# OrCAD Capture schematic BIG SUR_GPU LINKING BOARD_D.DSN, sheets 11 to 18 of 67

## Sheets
11 P11  PLX Switch-1 Straping: size Custom
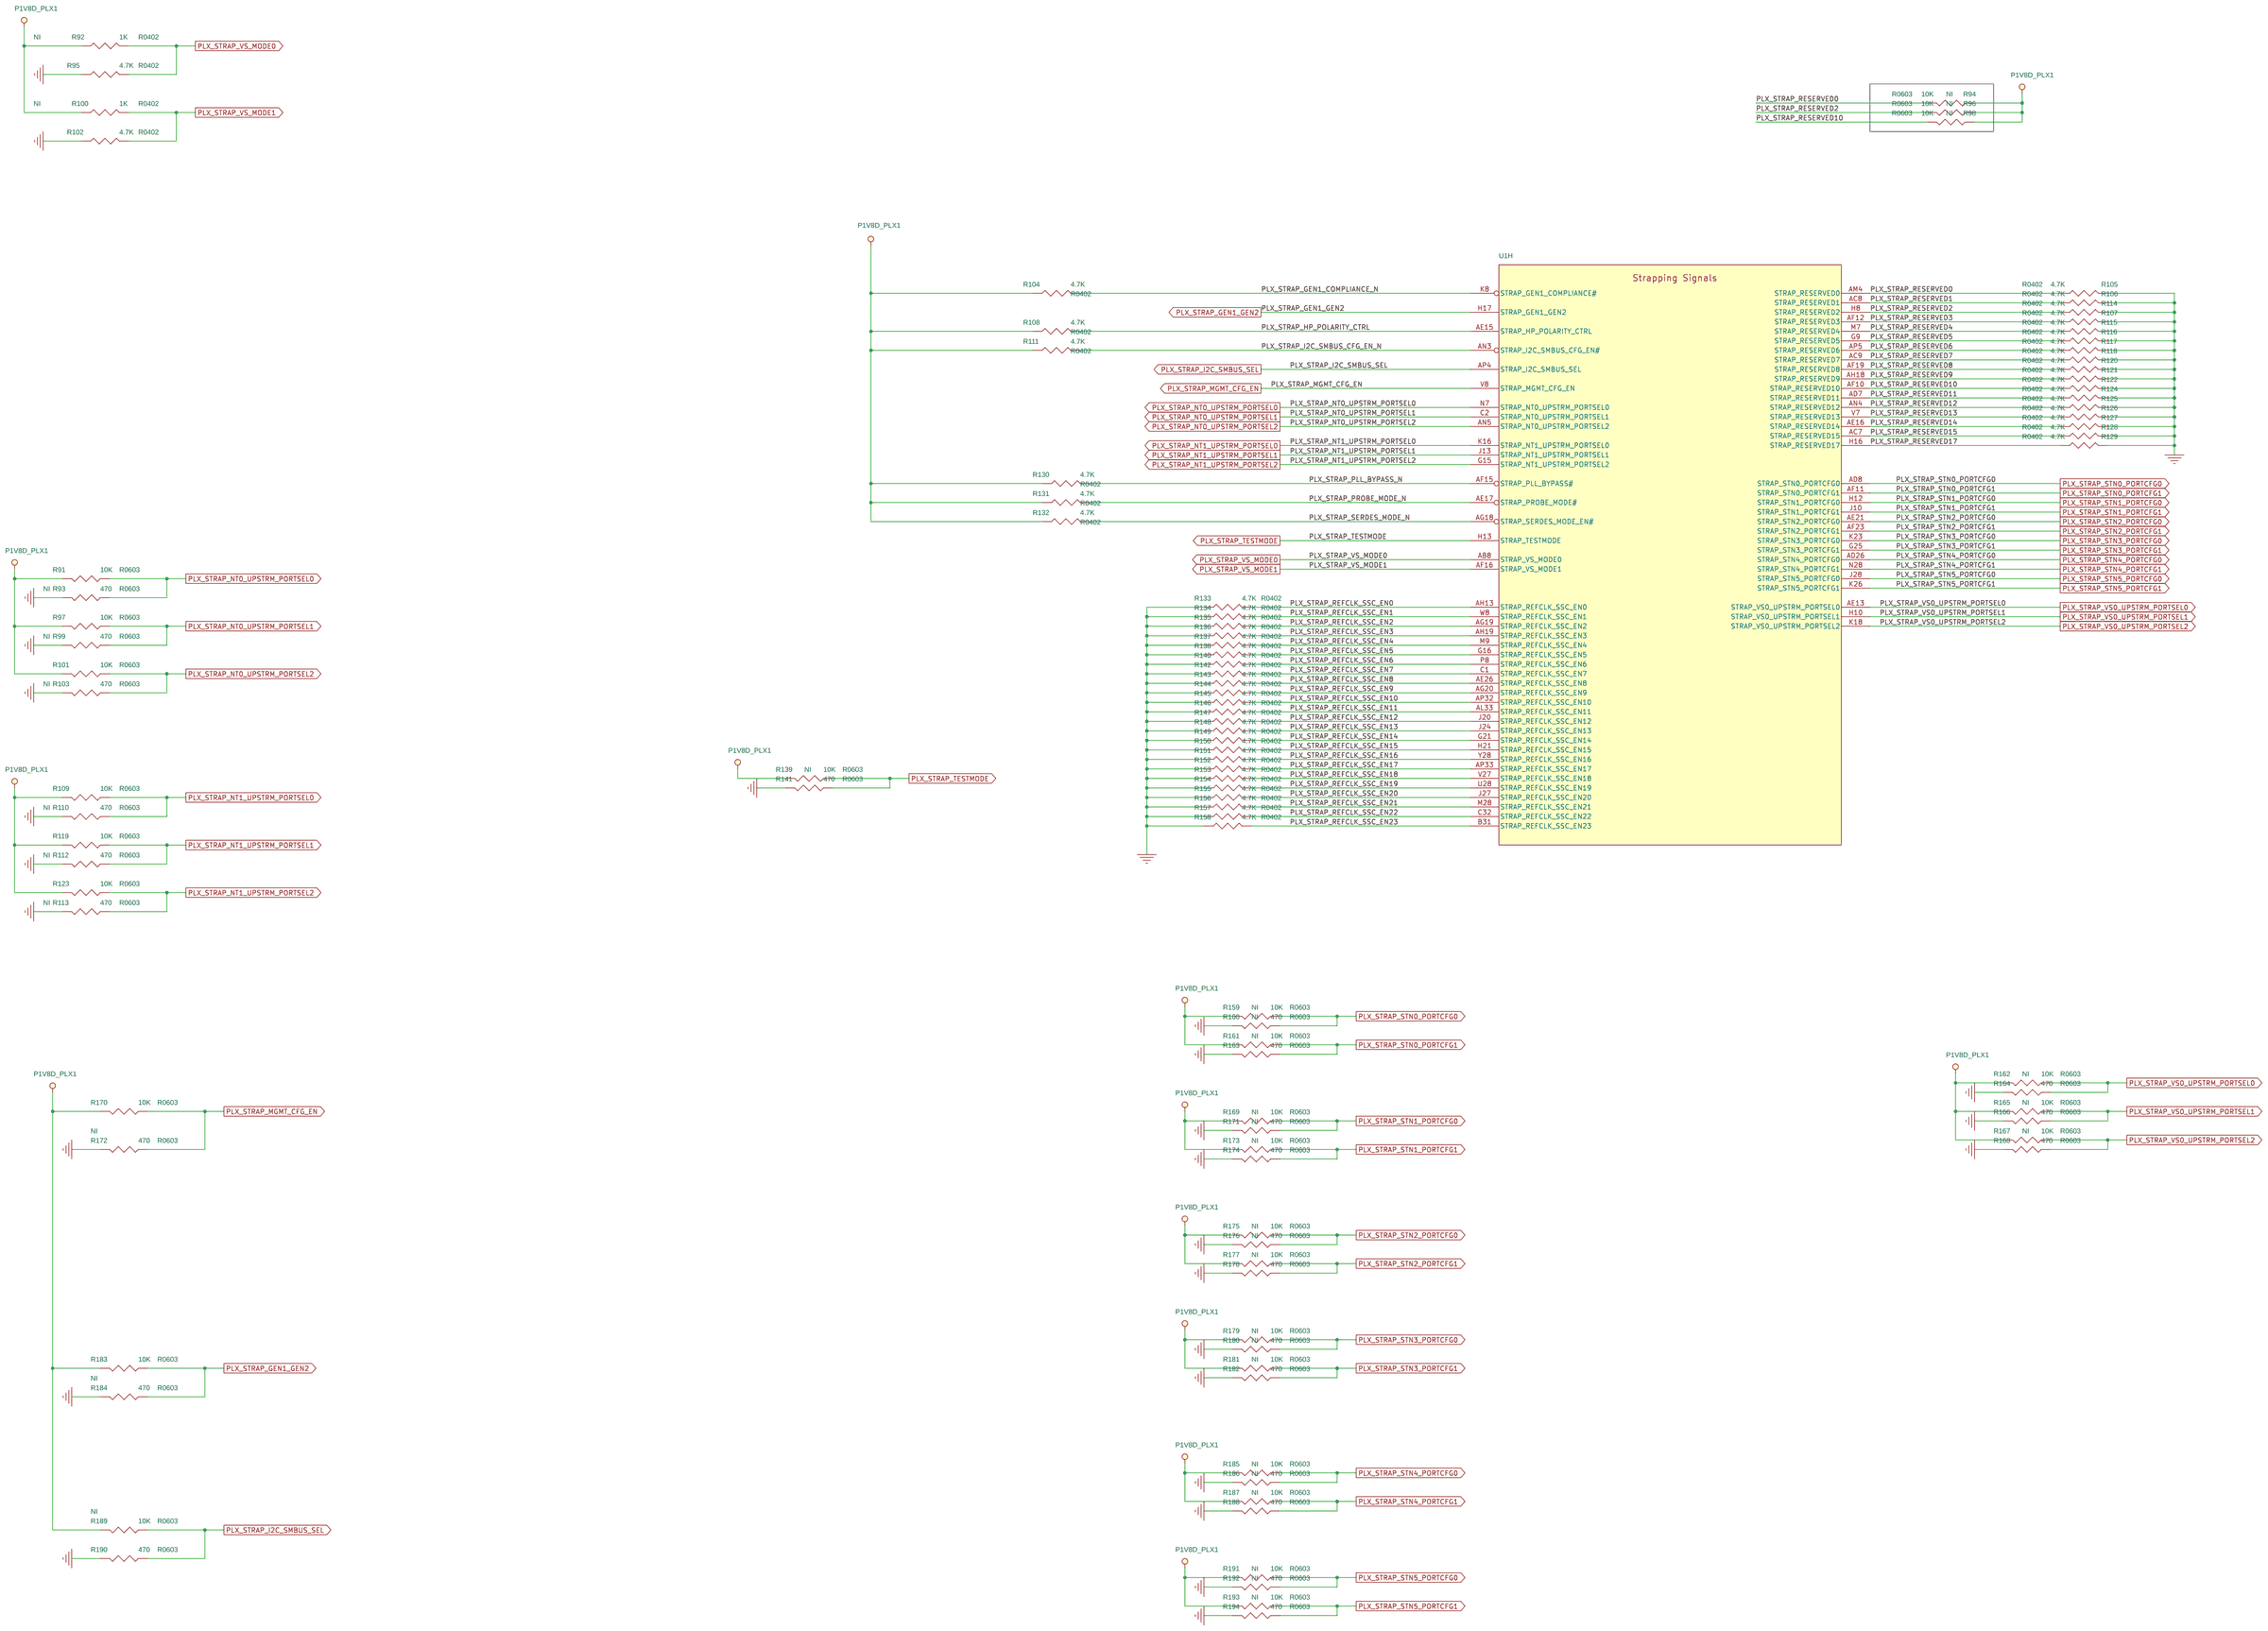
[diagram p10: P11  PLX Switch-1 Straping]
12 P12  PLX Switch-1 Power: size Custom
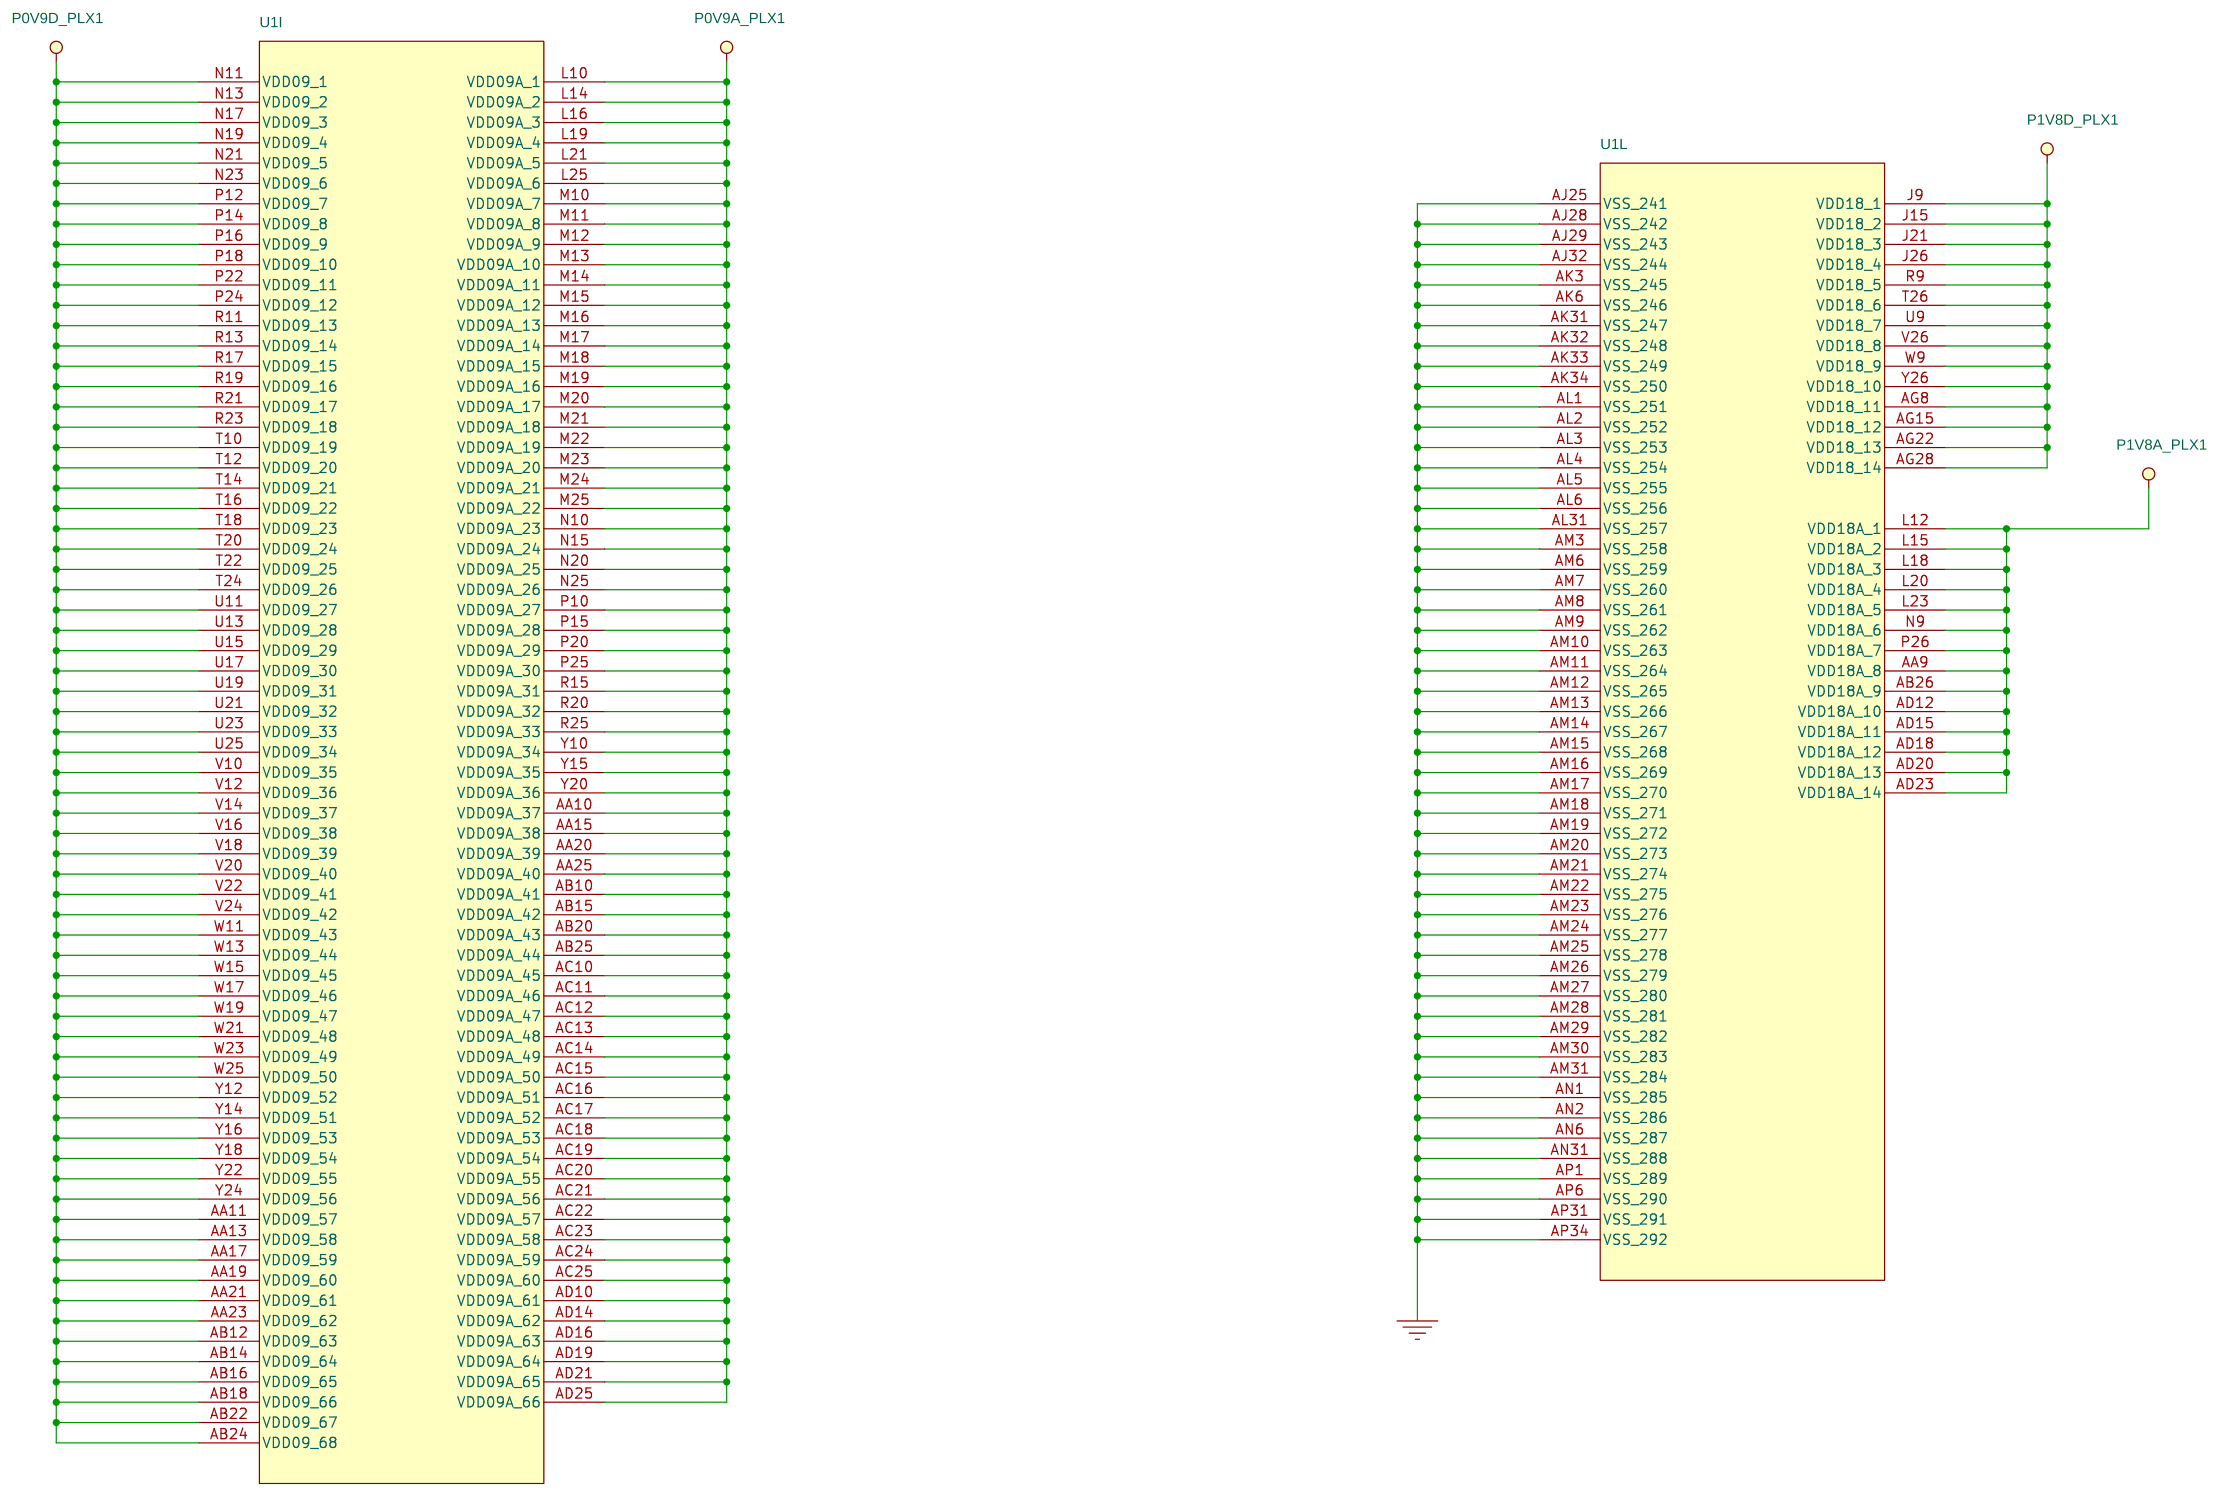
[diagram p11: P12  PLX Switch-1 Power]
13 P13  PLX Switch-1 VSS: size Custom
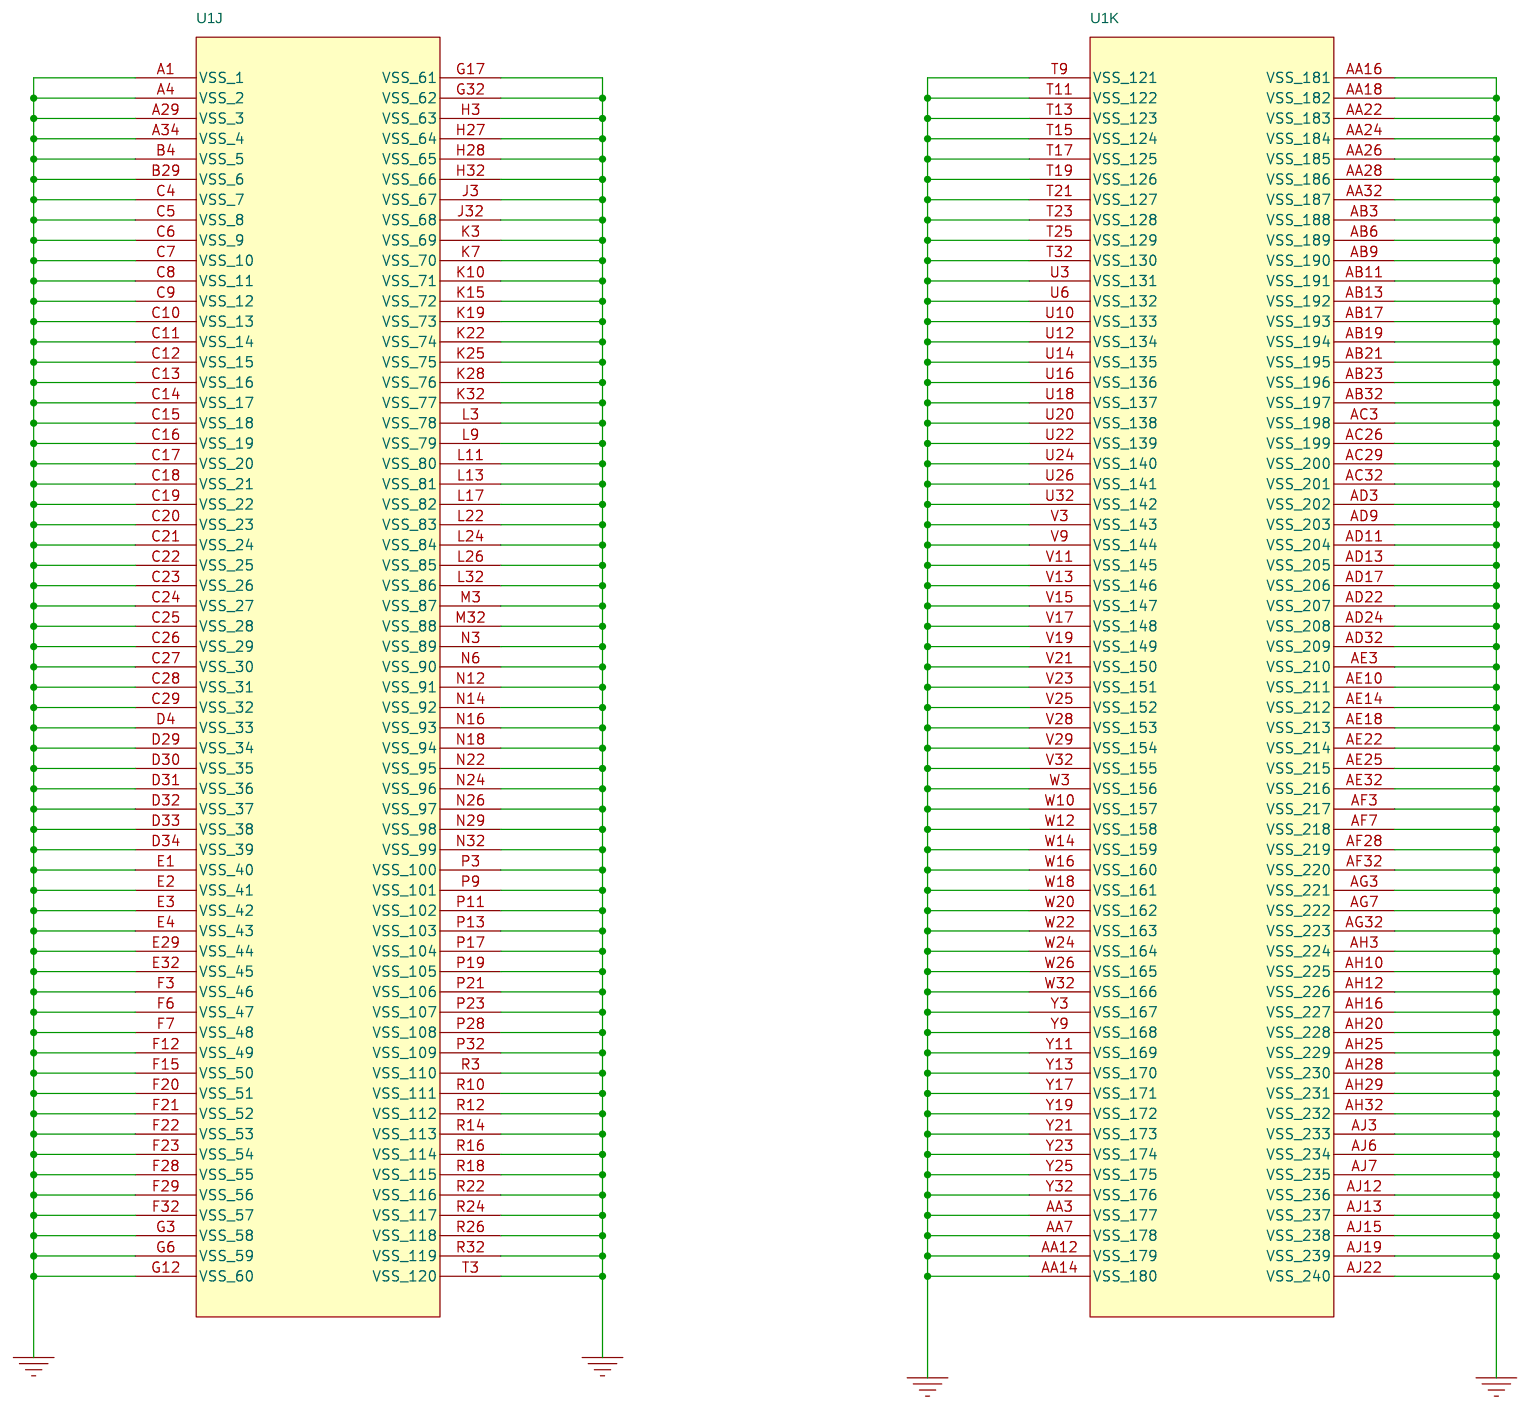
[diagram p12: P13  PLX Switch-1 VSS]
14 P14  PLX Switch-1 Decouping Cap: size Custom
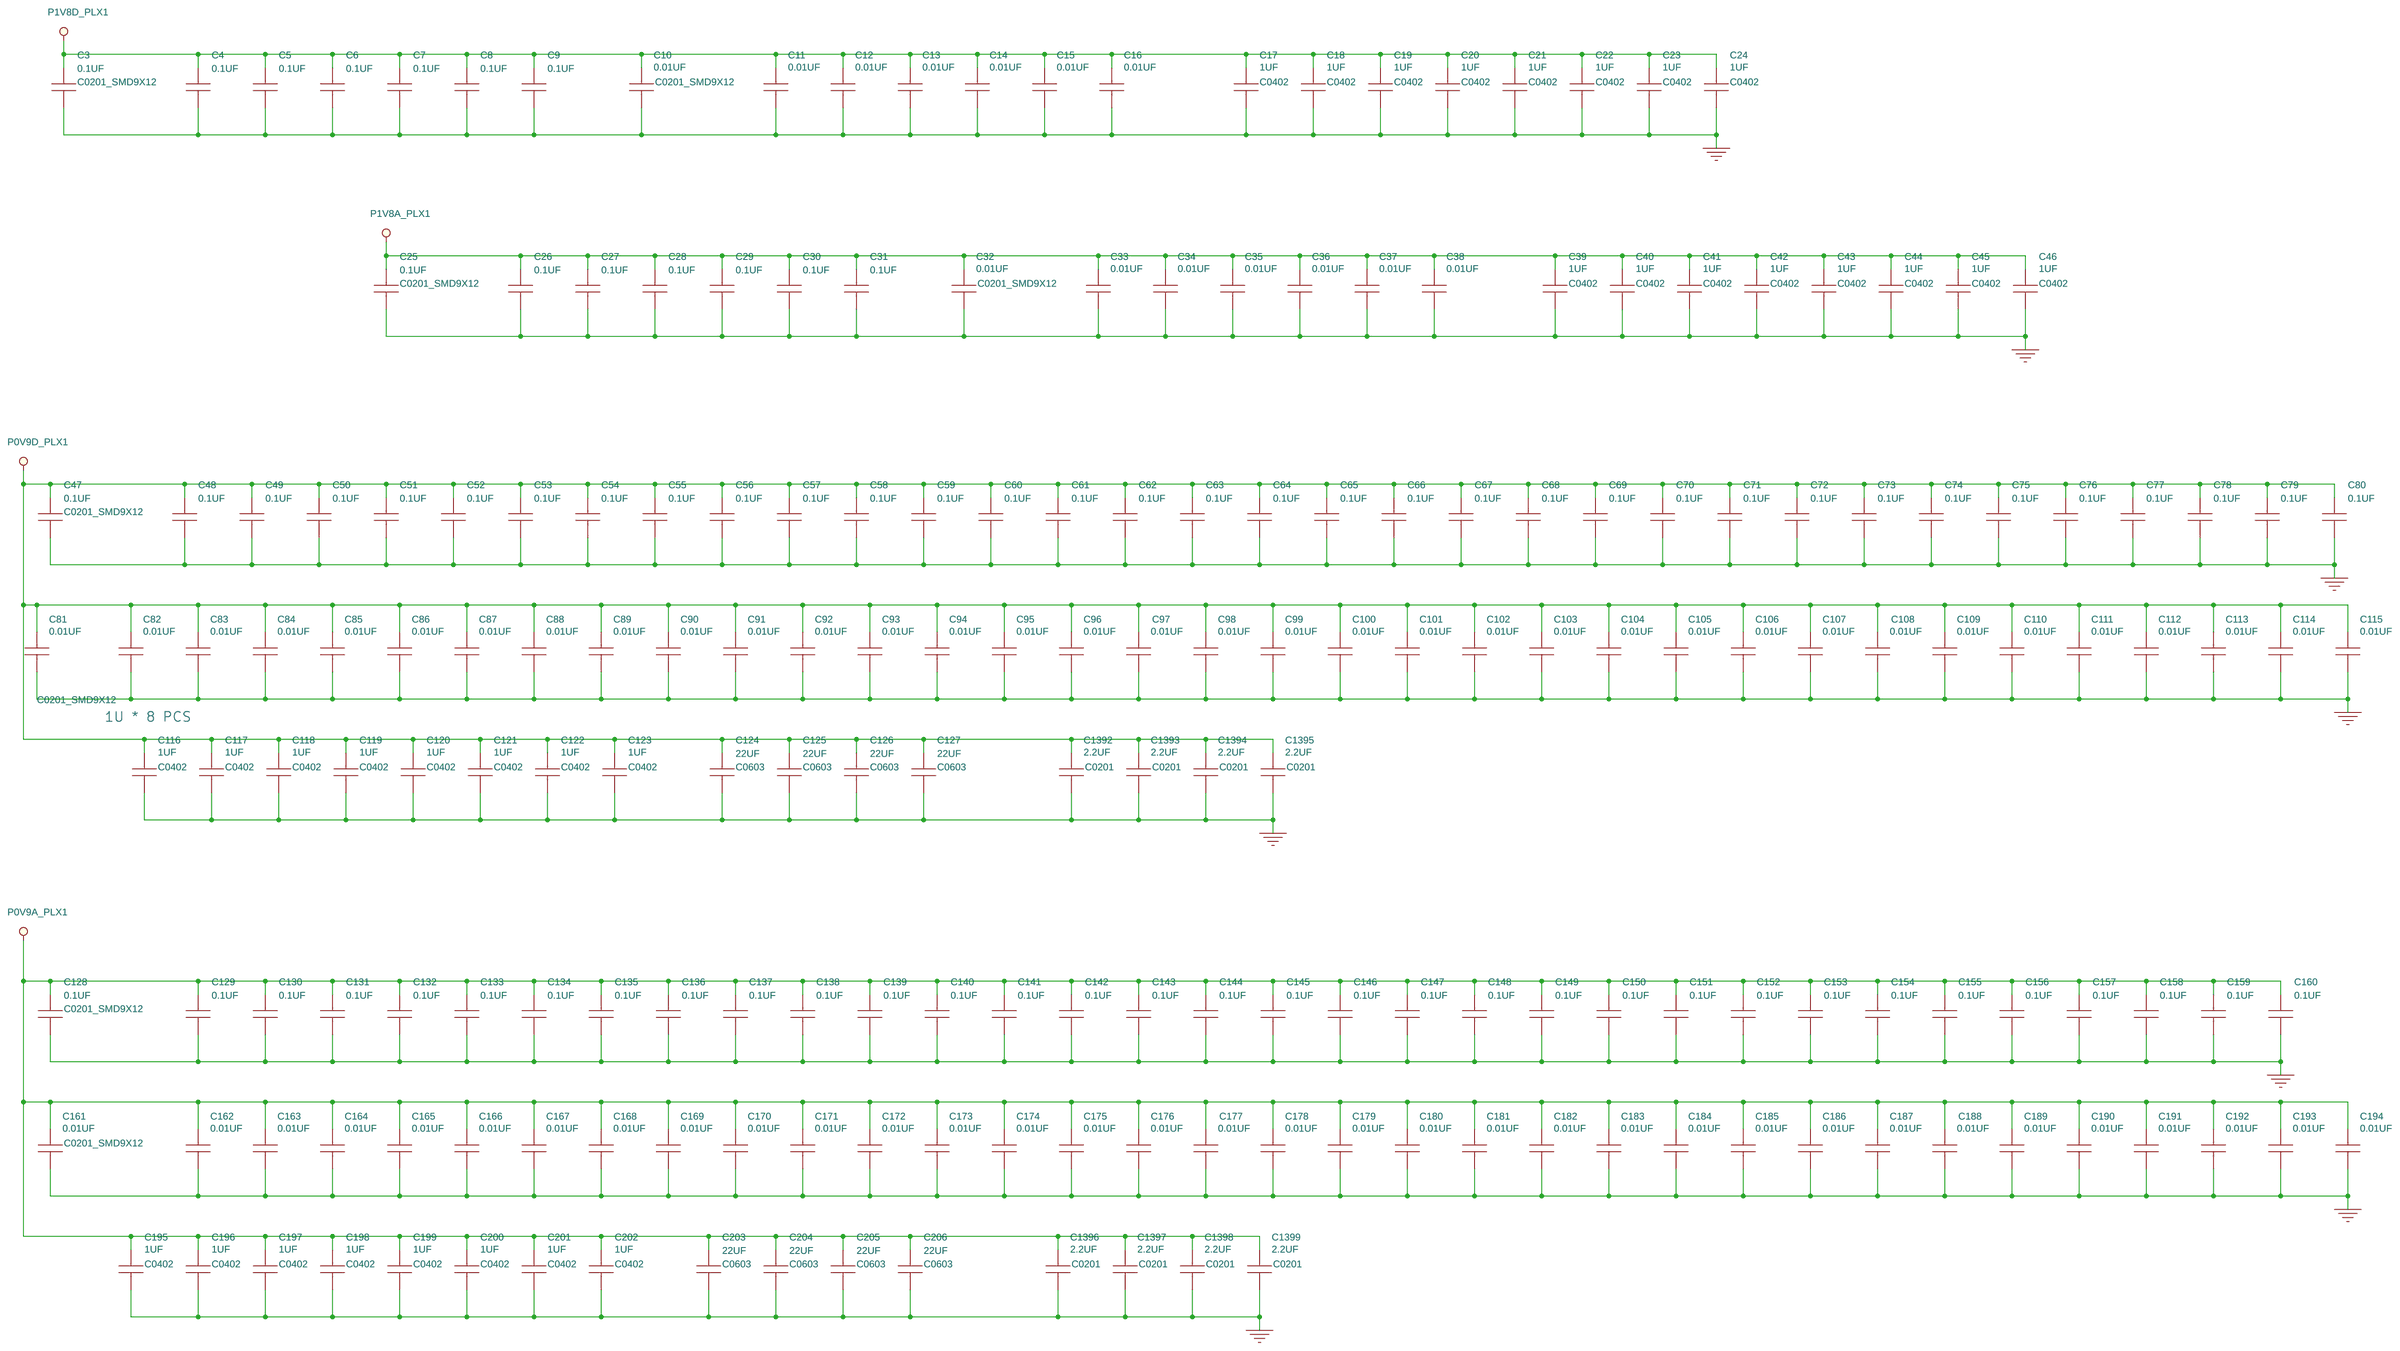
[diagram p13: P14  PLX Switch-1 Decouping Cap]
15 P15  PLX Switch-2 S0: size Custom
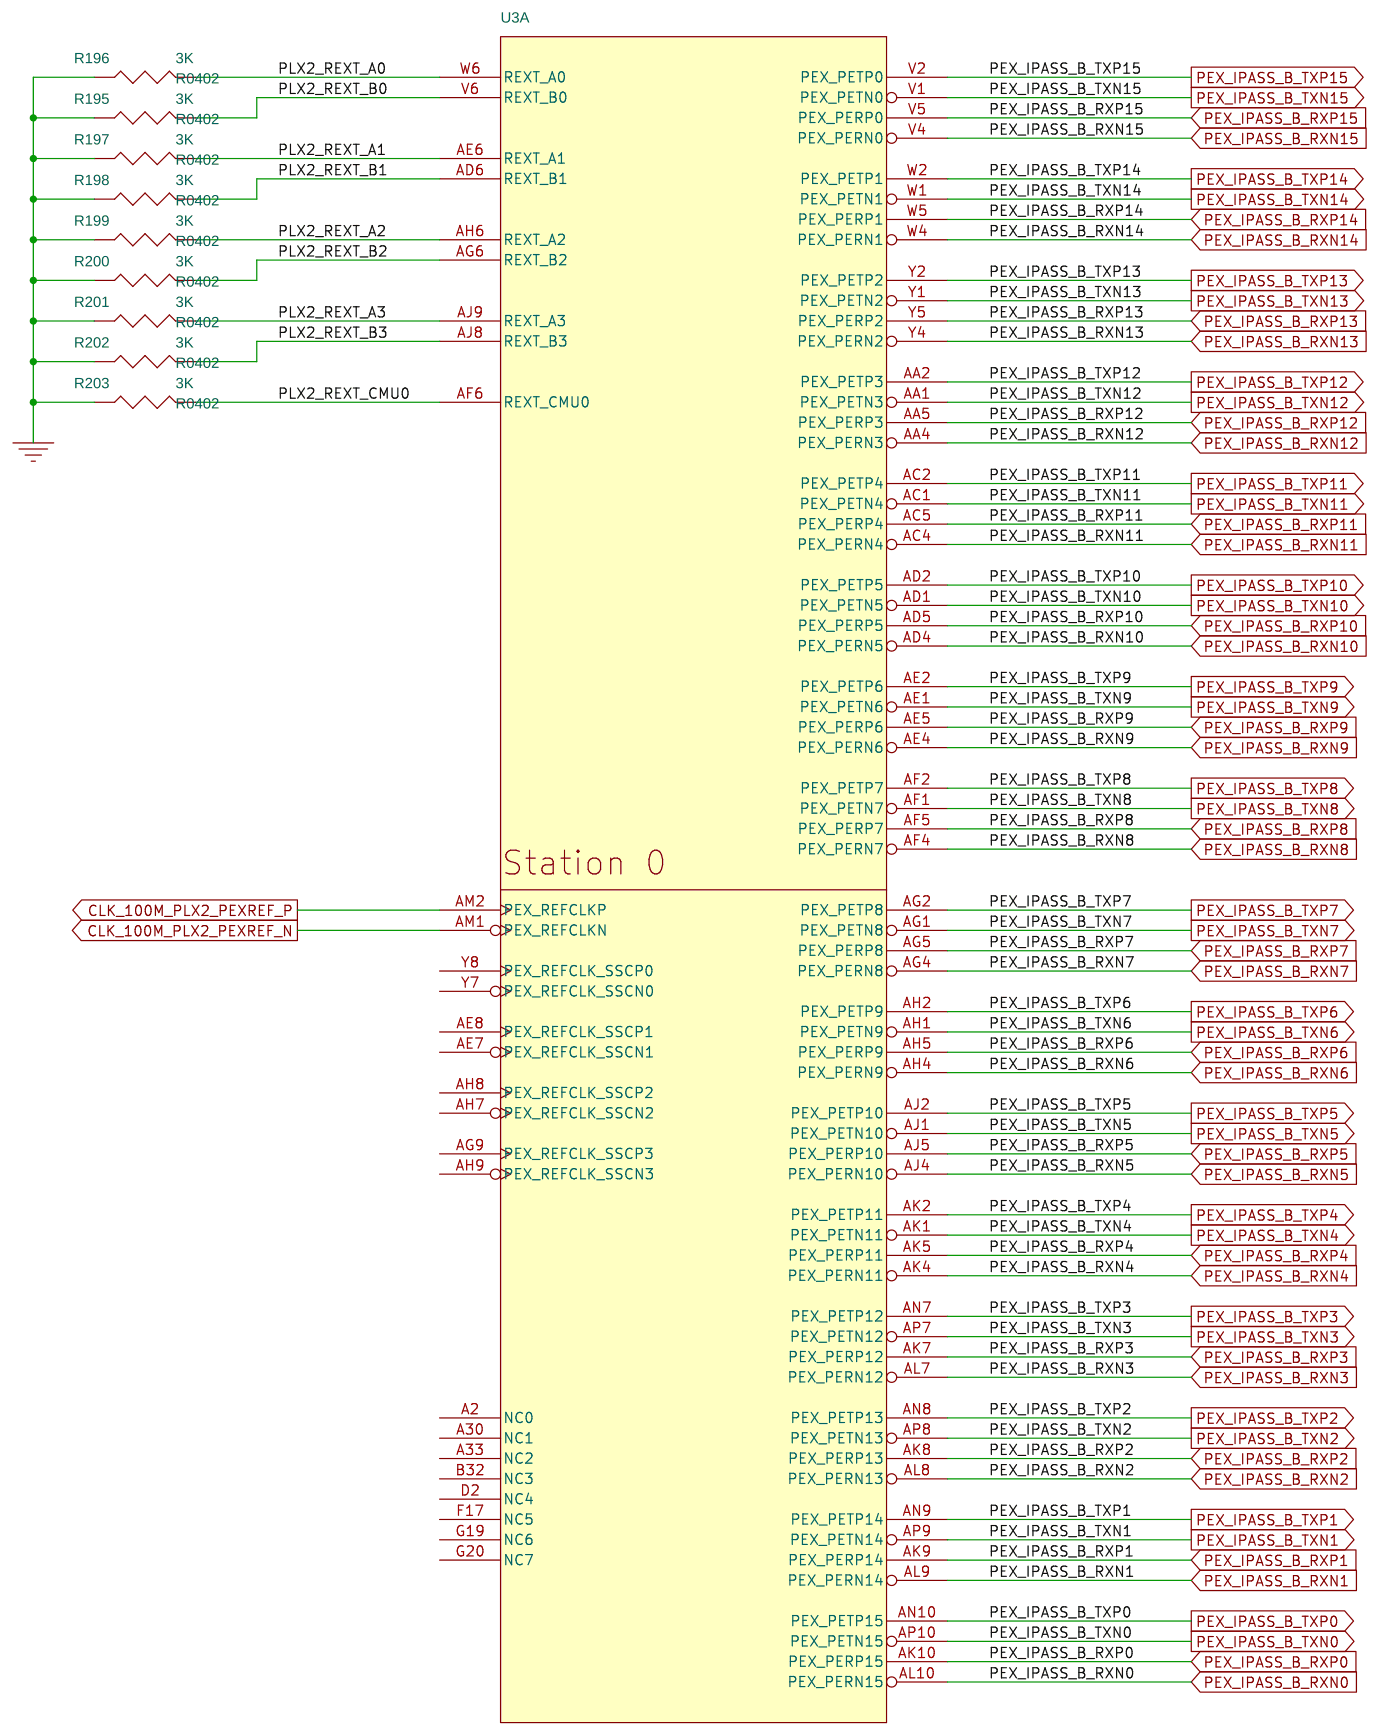
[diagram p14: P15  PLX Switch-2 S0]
16 P16  PLX Switch-2 S1: size Custom
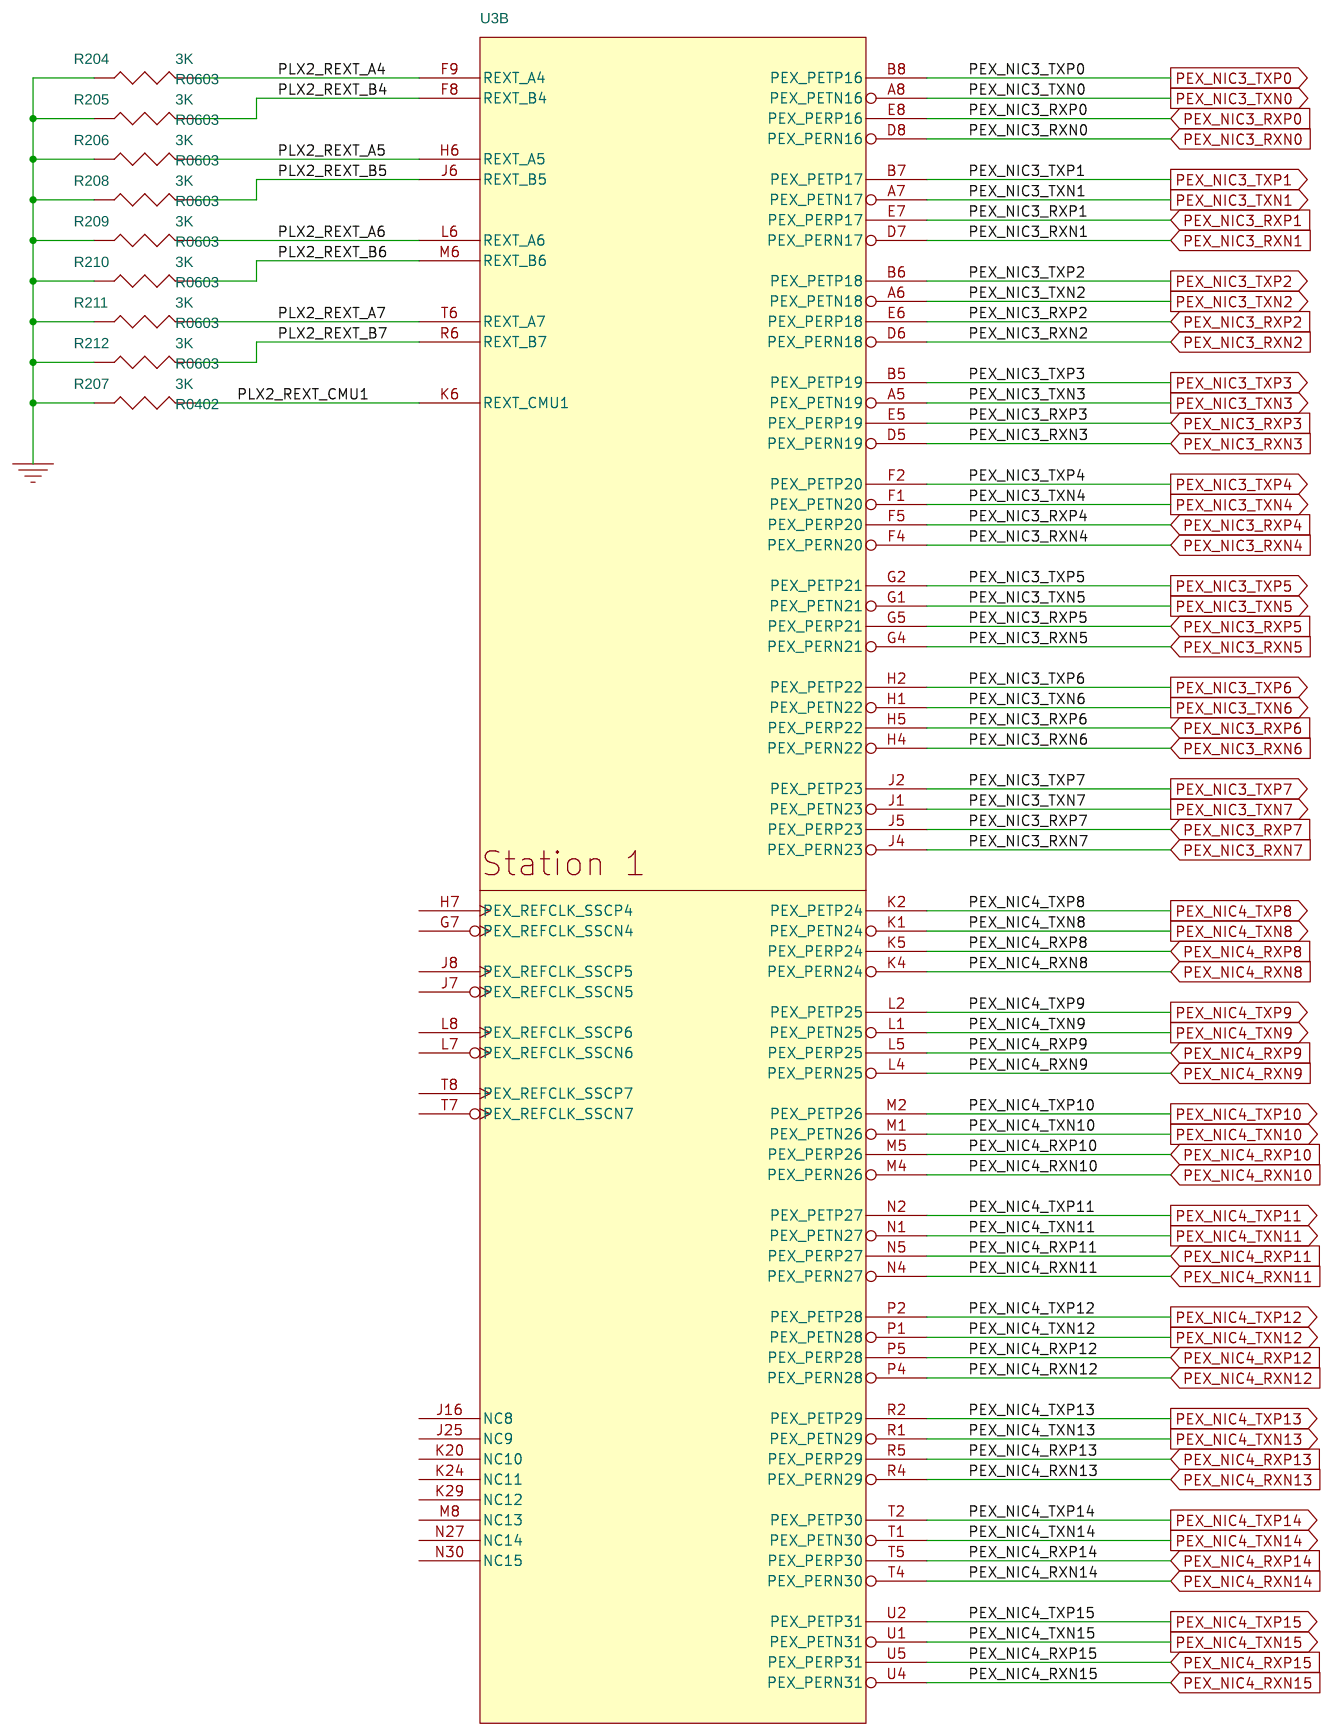
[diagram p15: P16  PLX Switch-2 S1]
17 P17  PLX Switch-2 S2: size Custom
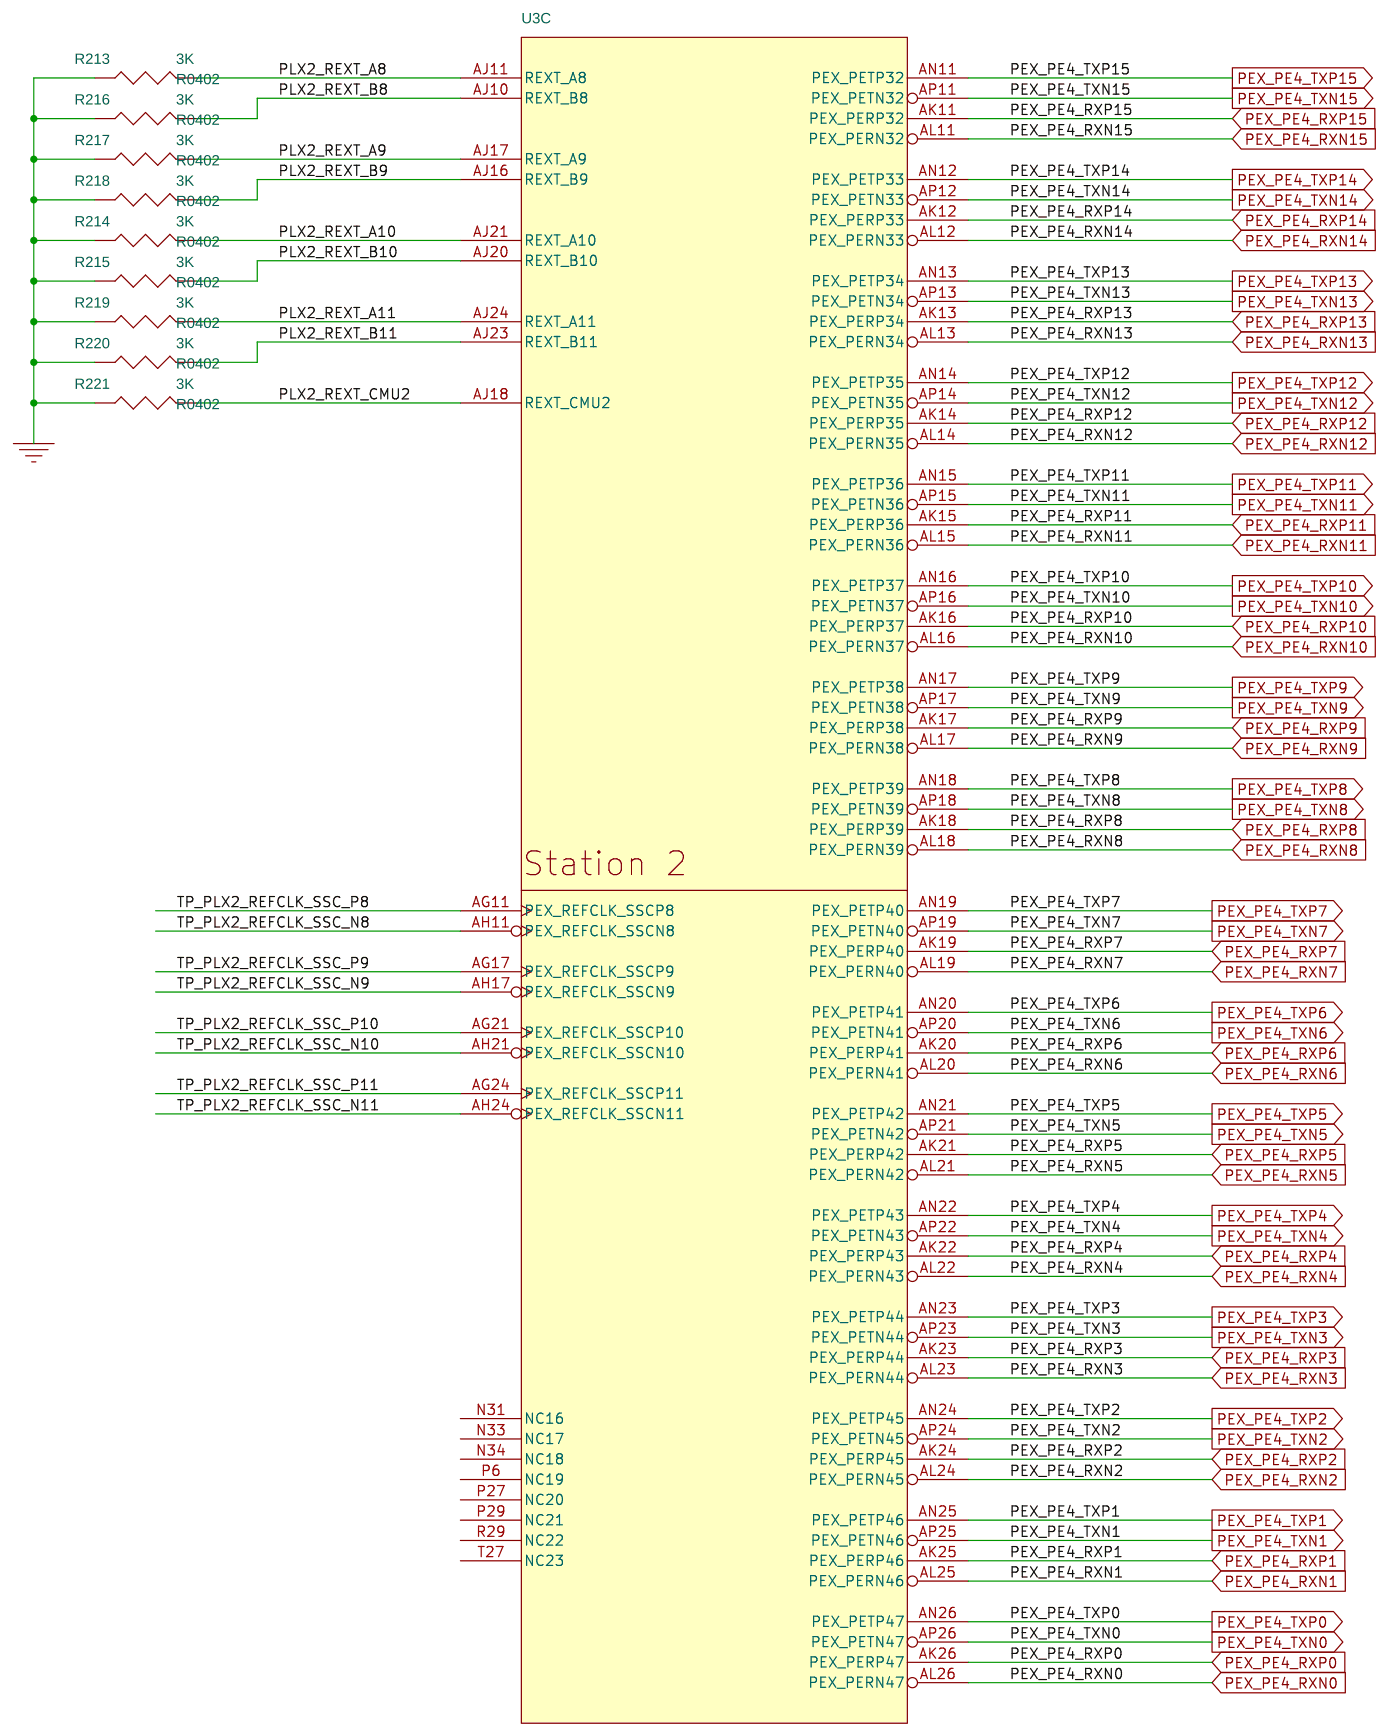
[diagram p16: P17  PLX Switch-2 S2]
18 P18  PLX Switch-2 S3: size Custom
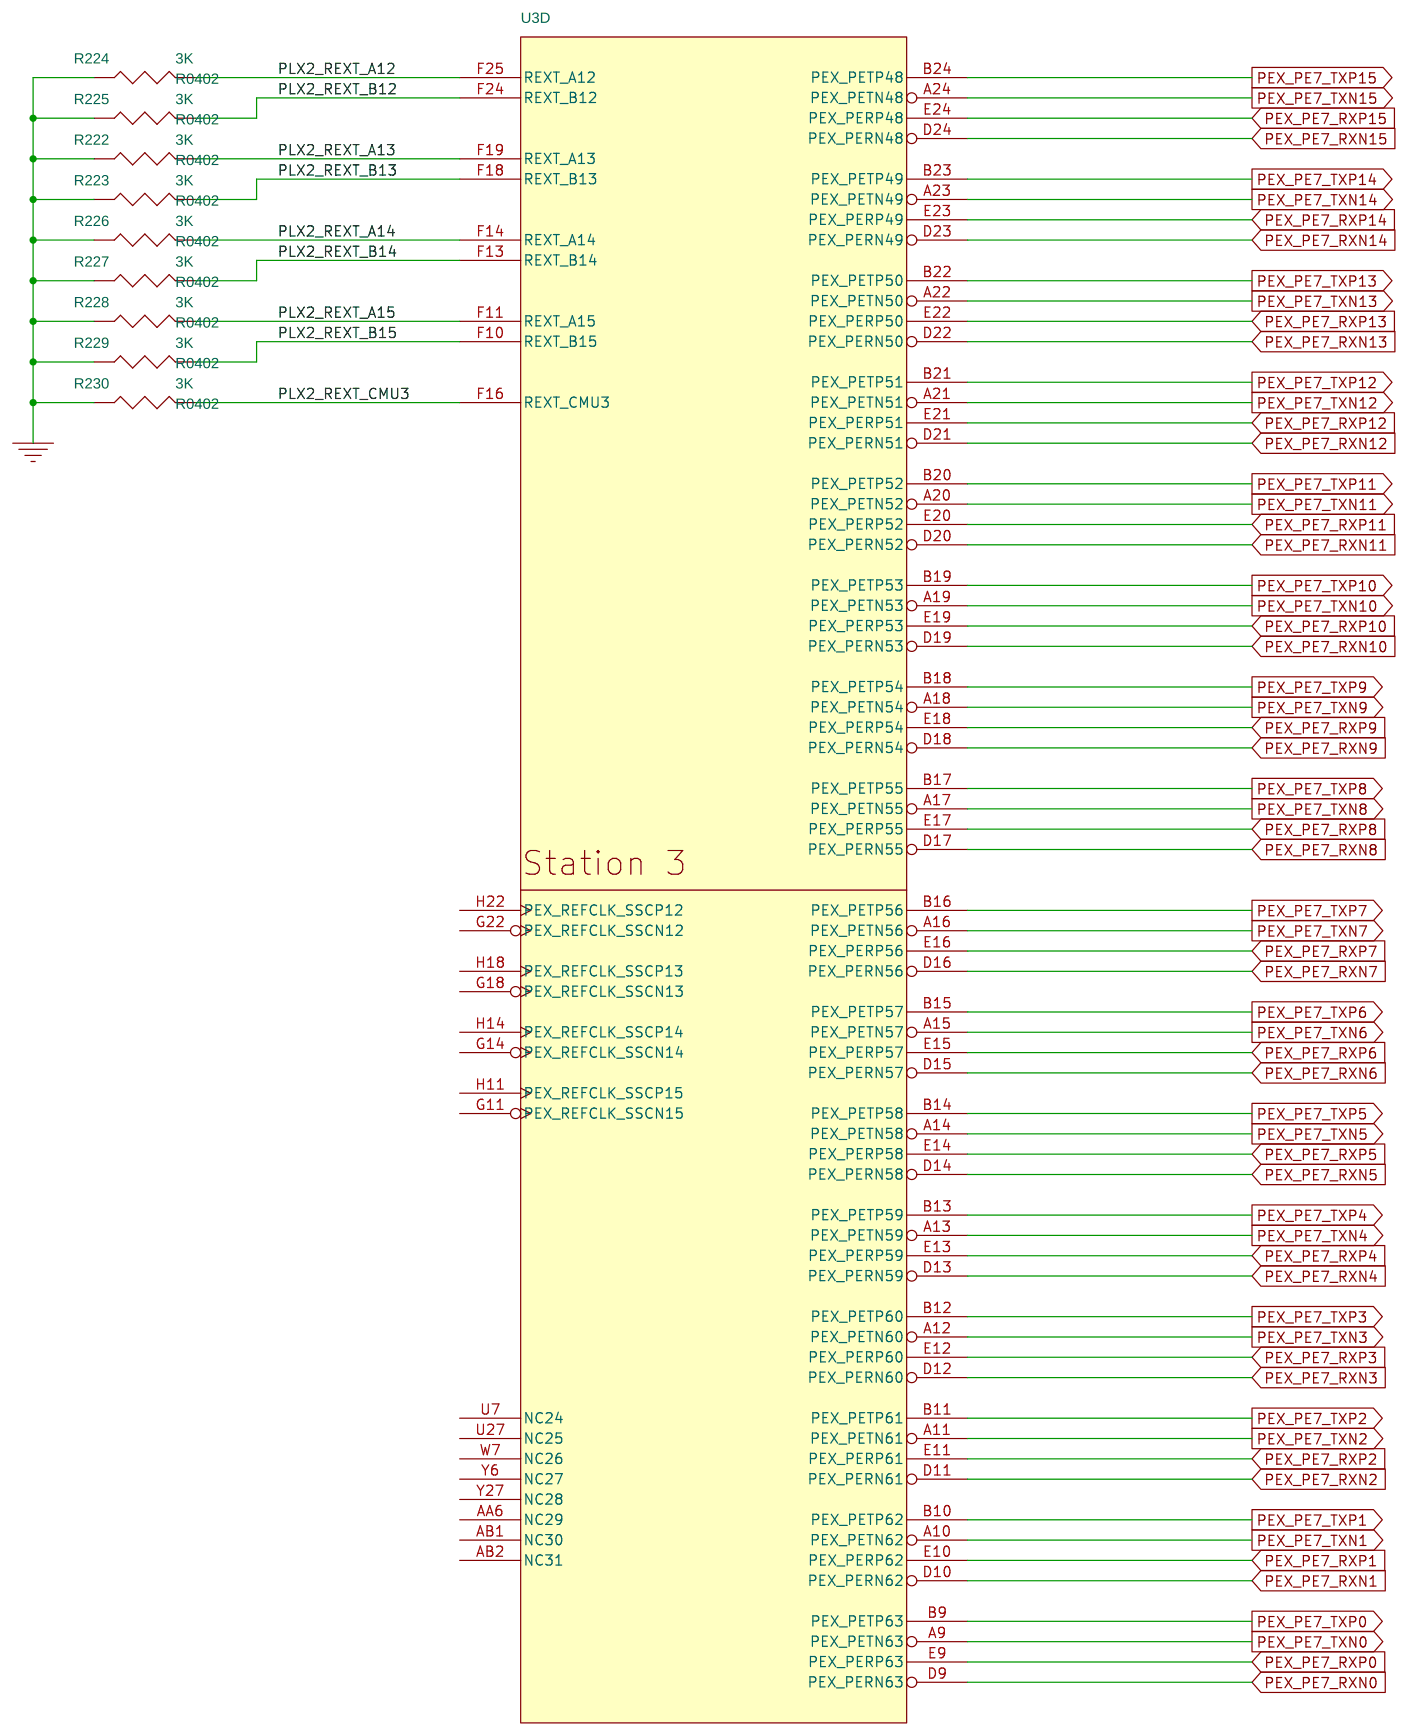
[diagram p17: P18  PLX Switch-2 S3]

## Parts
sheet P11  PLX Switch-1 Straping
R91  10K  [R0603]
R92  1K  [R0402]
R93  470  [R0603]
R94  10K  [R0603]
R95  4.7K  [R0402]
R96  10K  [R0603]
R97  10K  [R0603]
R98  10K  [R0603]
R99  470  [R0603]
R100  1K  [R0402]
R101  10K  [R0603]
R102  4.7K  [R0402]
R103  470  [R0603]
R104  4.7K  [R0402]
R105  4.7K  [R0402]
R106  4.7K  [R0402]
R107  4.7K  [R0402]
R108  4.7K  [R0402]
R109  10K  [R0603]
R110  470  [R0603]
R111  4.7K  [R0402]
R112  470  [R0603]
R113  470  [R0603]
R114  4.7K  [R0402]
R115  4.7K  [R0402]
R116  4.7K  [R0402]
R117  4.7K  [R0402]
R118  4.7K  [R0402]
R119  10K  [R0603]
R120  4.7K  [R0402]
R121  4.7K  [R0402]
R122  4.7K  [R0402]
R123  10K  [R0603]
R124  4.7K  [R0402]
R125  4.7K  [R0402]
R126  4.7K  [R0402]
R127  4.7K  [R0402]
R128  4.7K  [R0402]
R129  4.7K  [R0402]
R130  4.7K  [R0402]
R131  4.7K  [R0402]
R132  4.7K  [R0402]
R133  4.7K  [R0402]
R134  4.7K  [R0402]
R135  4.7K  [R0402]
R136  4.7K  [R0402]
R137  4.7K  [R0402]
R138  4.7K  [R0402]
R139  10K  [R0603]
R140  4.7K  [R0402]
R141  470  [R0603]
R142  4.7K  [R0402]
R143  4.7K  [R0402]
R144  4.7K  [R0402]
R145  4.7K  [R0402]
R146  4.7K  [R0402]
R147  4.7K  [R0402]
R148  4.7K  [R0402]
R149  4.7K  [R0402]
R150  4.7K  [R0402]
R151  4.7K  [R0402]
R152  4.7K  [R0402]
R153  4.7K  [R0402]
R154  4.7K  [R0402]
R155  4.7K  [R0402]
R156  4.7K  [R0402]
R157  4.7K  [R0402]
R158  4.7K  [R0402]
R159  10K  [R0603]
R160  470  [R0603]
R161  10K  [R0603]
R162  10K  [R0603]
R163  470  [R0603]
R164  470  [R0603]
R165  10K  [R0603]
R166  470  [R0603]
R167  10K  [R0603]
R168  470  [R0603]
R169  10K  [R0603]
R170  10K  [R0603]
R171  470  [R0603]
R172  470  [R0603]
R173  10K  [R0603]
R174  470  [R0603]
R175  10K  [R0603]
R176  470  [R0603]
R177  10K  [R0603]
R178  470  [R0603]
R179  10K  [R0603]
R180  470  [R0603]
R181  10K  [R0603]
R182  470  [R0603]
R183  10K  [R0603]
R184  470  [R0603]
R185  10K  [R0603]
R186  470  [R0603]
R187  10K  [R0603]
R188  470  [R0603]
R189  10K  [R0603]
R190  470  [R0603]
R191  10K  [R0603]
R192  470  [R0603]
R193  10K  [R0603]
R194  470  [R0603]
U1  PLX  [BGA1156]  (sections A,B,C,D,E,F,G,H,I,J,K,L)
sheet P14  PLX Switch-1 Decouping Cap
C3  0.1UF  [C0201_SMD9X12]
C4  0.1UF  [C0201_SMD9X12]
C5  0.1UF  [C0201_SMD9X12]
C6  0.1UF  [C0201_SMD9X12]
C7  0.1UF  [C0201_SMD9X12]
C8  0.1UF  [C0201_SMD9X12]
C9  0.1UF  [C0201_SMD9X12]
C10  0.01UF  [C0201_SMD9X12]
C11  0.01UF  [C0201_SMD9X12]
C12  0.01UF  [C0201_SMD9X12]
C13  0.01UF  [C0201_SMD9X12]
C14  0.01UF  [C0201_SMD9X12]
C15  0.01UF  [C0201_SMD9X12]
C16  0.01UF  [C0201_SMD9X12]
C17  1UF  [C0402]
C18  1UF  [C0402]
C19  1UF  [C0402]
C20  1UF  [C0402]
C21  1UF  [C0402]
C22  1UF  [C0402]
C23  1UF  [C0402]
C24  1UF  [C0402]
C25  0.1UF  [C0201_SMD9X12]
C26  0.1UF  [C0201_SMD9X12]
C27  0.1UF  [C0201_SMD9X12]
C28  0.1UF  [C0201_SMD9X12]
C29  0.1UF  [C0201_SMD9X12]
C30  0.1UF  [C0201_SMD9X12]
C31  0.1UF  [C0201_SMD9X12]
C32  0.01UF  [C0201_SMD9X12]
C33  0.01UF  [C0201_SMD9X12]
C34  0.01UF  [C0201_SMD9X12]
C35  0.01UF  [C0201_SMD9X12]
C36  0.01UF  [C0201_SMD9X12]
C37  0.01UF  [C0201_SMD9X12]
C38  0.01UF  [C0201_SMD9X12]
C39  1UF  [C0402]
C40  1UF  [C0402]
C41  1UF  [C0402]
C42  1UF  [C0402]
C43  1UF  [C0402]
C44  1UF  [C0402]
C45  1UF  [C0402]
C46  1UF  [C0402]
C47  0.1UF  [C0201_SMD9X12]
C48  0.1UF  [C0201_SMD9X12]
C49  0.1UF  [C0201_SMD9X12]
C50  0.1UF  [C0201_SMD9X12]
C51  0.1UF  [C0201_SMD9X12]
C52  0.1UF  [C0201_SMD9X12]
C53  0.1UF  [C0201_SMD9X12]
C54  0.1UF  [C0201_SMD9X12]
C55  0.1UF  [C0201_SMD9X12]
C56  0.1UF  [C0201_SMD9X12]
C57  0.1UF  [C0201_SMD9X12]
C58  0.1UF  [C0201_SMD9X12]
C59  0.1UF  [C0201_SMD9X12]
C60  0.1UF  [C0201_SMD9X12]
C61  0.1UF  [C0201_SMD9X12]
C62  0.1UF  [C0201_SMD9X12]
C63  0.1UF  [C0201_SMD9X12]
C64  0.1UF  [C0201_SMD9X12]
C65  0.1UF  [C0201_SMD9X12]
C66  0.1UF  [C0201_SMD9X12]
C67  0.1UF  [C0201_SMD9X12]
C68  0.1UF  [C0201_SMD9X12]
C69  0.1UF  [C0201_SMD9X12]
C70  0.1UF  [C0201_SMD9X12]
C71  0.1UF  [C0201_SMD9X12]
C72  0.1UF  [C0201_SMD9X12]
C73  0.1UF  [C0201_SMD9X12]
C74  0.1UF  [C0201_SMD9X12]
C75  0.1UF  [C0201_SMD9X12]
C76  0.1UF  [C0201_SMD9X12]
C77  0.1UF  [C0201_SMD9X12]
C78  0.1UF  [C0201_SMD9X12]
C79  0.1UF  [C0201_SMD9X12]
C80  0.1UF  [C0201_SMD9X12]
C81  0.01UF  [C0201_SMD9X12]
C82  0.01UF  [C0201_SMD9X12]
C83  0.01UF  [C0201_SMD9X12]
C84  0.01UF  [C0201_SMD9X12]
C85  0.01UF  [C0201_SMD9X12]
C86  0.01UF  [C0201_SMD9X12]
C87  0.01UF  [C0201_SMD9X12]
C88  0.01UF  [C0201_SMD9X12]
C89  0.01UF  [C0201_SMD9X12]
C90  0.01UF  [C0201_SMD9X12]
C91  0.01UF  [C0201_SMD9X12]
C92  0.01UF  [C0201_SMD9X12]
C93  0.01UF  [C0201_SMD9X12]
C94  0.01UF  [C0201_SMD9X12]
C95  0.01UF  [C0201_SMD9X12]
C96  0.01UF  [C0201_SMD9X12]
C97  0.01UF  [C0201_SMD9X12]
C98  0.01UF  [C0201_SMD9X12]
C99  0.01UF  [C0201_SMD9X12]
C100  0.01UF  [C0201_SMD9X12]
C101  0.01UF  [C0201_SMD9X12]
C102  0.01UF  [C0201_SMD9X12]
C103  0.01UF  [C0201_SMD9X12]
C104  0.01UF  [C0201_SMD9X12]
C105  0.01UF  [C0201_SMD9X12]
C106  0.01UF  [C0201_SMD9X12]
C107  0.01UF  [C0201_SMD9X12]
C108  0.01UF  [C0201_SMD9X12]
C109  0.01UF  [C0201_SMD9X12]
C110  0.01UF  [C0201_SMD9X12]
C111  0.01UF  [C0201_SMD9X12]
C112  0.01UF  [C0201_SMD9X12]
C113  0.01UF  [C0201_SMD9X12]
C114  0.01UF  [C0201_SMD9X12]
C115  0.01UF  [C0201_SMD9X12]
C116  1UF  [C0402]
C117  1UF  [C0402]
C118  1UF  [C0402]
C119  1UF  [C0402]
C120  1UF  [C0402]
C121  1UF  [C0402]
C122  1UF  [C0402]
C123  1UF  [C0402]
C124  22UF  [C0603]
C125  22UF  [C0603]
C126  22UF  [C0603]
C127  22UF  [C0603]
C128  0.1UF  [C0201_SMD9X12]
C129  0.1UF  [C0201_SMD9X12]
C130  0.1UF  [C0201_SMD9X12]
C131  0.1UF  [C0201_SMD9X12]
C132  0.1UF  [C0201_SMD9X12]
C133  0.1UF  [C0201_SMD9X12]
C134  0.1UF  [C0201_SMD9X12]
C135  0.1UF  [C0201_SMD9X12]
C136  0.1UF  [C0201_SMD9X12]
C137  0.1UF  [C0201_SMD9X12]
C138  0.1UF  [C0201_SMD9X12]
C139  0.1UF  [C0201_SMD9X12]
C140  0.1UF  [C0201_SMD9X12]
C141  0.1UF  [C0201_SMD9X12]
C142  0.1UF  [C0201_SMD9X12]
C143  0.1UF  [C0201_SMD9X12]
C144  0.1UF  [C0201_SMD9X12]
C145  0.1UF  [C0201_SMD9X12]
C146  0.1UF  [C0201_SMD9X12]
C147  0.1UF  [C0201_SMD9X12]
C148  0.1UF  [C0201_SMD9X12]
C149  0.1UF  [C0201_SMD9X12]
C150  0.1UF  [C0201_SMD9X12]
C151  0.1UF  [C0201_SMD9X12]
C152  0.1UF  [C0201_SMD9X12]
C153  0.1UF  [C0201_SMD9X12]
C154  0.1UF  [C0201_SMD9X12]
C155  0.1UF  [C0201_SMD9X12]
C156  0.1UF  [C0201_SMD9X12]
C157  0.1UF  [C0201_SMD9X12]
C158  0.1UF  [C0201_SMD9X12]
C159  0.1UF  [C0201_SMD9X12]
C160  0.1UF  [C0201_SMD9X12]
C161  0.01UF  [C0201_SMD9X12]
C162  0.01UF  [C0201_SMD9X12]
C163  0.01UF  [C0201_SMD9X12]
C164  0.01UF  [C0201_SMD9X12]
C165  0.01UF  [C0201_SMD9X12]
C166  0.01UF  [C0201_SMD9X12]
C167  0.01UF  [C0201_SMD9X12]
C168  0.01UF  [C0201_SMD9X12]
C169  0.01UF  [C0201_SMD9X12]
C170  0.01UF  [C0201_SMD9X12]
C171  0.01UF  [C0201_SMD9X12]
C172  0.01UF  [C0201_SMD9X12]
C173  0.01UF  [C0201_SMD9X12]
C174  0.01UF  [C0201_SMD9X12]
C175  0.01UF  [C0201_SMD9X12]
C176  0.01UF  [C0201_SMD9X12]
C177  0.01UF  [C0201_SMD9X12]
C178  0.01UF  [C0201_SMD9X12]
C179  0.01UF  [C0201_SMD9X12]
C180  0.01UF  [C0201_SMD9X12]
C181  0.01UF  [C0201_SMD9X12]
C182  0.01UF  [C0201_SMD9X12]
C183  0.01UF  [C0201_SMD9X12]
C184  0.01UF  [C0201_SMD9X12]
C185  0.01UF  [C0201_SMD9X12]
C186  0.01UF  [C0201_SMD9X12]
C187  0.01UF  [C0201_SMD9X12]
C188  0.01UF  [C0201_SMD9X12]
C189  0.01UF  [C0201_SMD9X12]
C190  0.01UF  [C0201_SMD9X12]
C191  0.01UF  [C0201_SMD9X12]
C192  0.01UF  [C0201_SMD9X12]
C193  0.01UF  [C0201_SMD9X12]
C194  0.01UF  [C0201_SMD9X12]
C195  1UF  [C0402]
C196  1UF  [C0402]
C197  1UF  [C0402]
C198  1UF  [C0402]
C199  1UF  [C0402]
C200  1UF  [C0402]
C201  1UF  [C0402]
C202  1UF  [C0402]
C203  22UF  [C0603]
C204  22UF  [C0603]
C205  22UF  [C0603]
C206  22UF  [C0603]
C1392  2.2UF  [C0201]
C1393  2.2UF  [C0201]
C1394  2.2UF  [C0201]
C1395  2.2UF  [C0201]
C1396  2.2UF  [C0201]
C1397  2.2UF  [C0201]
C1398  2.2UF  [C0201]
C1399  2.2UF  [C0201]
sheet P15  PLX Switch-2 S0
R195  3K  [R0402]
R196  3K  [R0402]
R197  3K  [R0402]
R198  3K  [R0402]
R199  3K  [R0402]
R200  3K  [R0402]
R201  3K  [R0402]
R202  3K  [R0402]
R203  3K  [R0402]
sheet P16  PLX Switch-2 S1
R204  3K  [R0603]
R205  3K  [R0603]
R206  3K  [R0603]
R207  3K  [R0402]
R208  3K  [R0603]
R209  3K  [R0603]
R210  3K  [R0603]
R211  3K  [R0603]
R212  3K  [R0603]
sheet P17  PLX Switch-2 S2
R213  3K  [R0402]
R214  3K  [R0402]
R215  3K  [R0402]
R216  3K  [R0402]
R217  3K  [R0402]
R218  3K  [R0402]
R219  3K  [R0402]
R220  3K  [R0402]
R221  3K  [R0402]
sheet P18  PLX Switch-2 S3
R222  3K  [R0402]
R223  3K  [R0402]
R224  3K  [R0402]
R225  3K  [R0402]
R226  3K  [R0402]
R227  3K  [R0402]
R228  3K  [R0402]
R229  3K  [R0402]
R230  3K  [R0402]
sheet P21  PLX Switch-2 Mode Select
U3  PLX  [BGA1156]  (sections A,B,C,D,E,F,G,H,I,J,K,L)

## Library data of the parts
R91 R97 R101 R109 R119 R123 R141 R163 R164 R166 R168 R170 R174 R178 R182 R183 R188 R190 R194 R204-R206 R208-R212 = R: Part_Type: *LF_Resistor; WATTAGE: 1/10W
R92 R100 = R: Not_insert: NI; Part_Type: *LF_Resistor; WATTAGE: 1/16W
R93 R94 R96 R98 R99 R103 R110 R112 R113 R139 R159-R162 R165 R167 R169 R171-R173 R175-R177 R179-R181 R184-R187 R189 R191-R193 = R: Not_insert: NI; Part_Type: *LF_Resistor; WATTAGE: 1/10W
R95 R102 R104-R108 R111 R114-R118 R120-R122 R124-R138 R140 R142-R158 R195-R203 R207 R213-R230 = R: Part_Type: *LF_Resistor; WATTAGE: 1/16W
U1 U3 = PEX8796AA80BIG: Part_Type: *LF_Chipset
C3-C16 C25-C38 C47-C115 C128-C194 C1392-C1399 = CAP_NP: Part_Type: *LF_C0201
C17-C24 C39-C46 C116-C123 C195-C202 = CAP_NP: Part_Type: *LF_C0402
C124-C127 C203-C206 = CAP_NP: Part_Type: *LF_C0603

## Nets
GND: C3.2 C4.2 C5.2 C6.2 C7.2 C8.2 C9.2 C10.2 C11.2 C12.2 C13.2 C14.2 C15.2 C16.2 C17.2 C18.2 C19.2 C20.2 C21.2 C22.2 C23.2 C24.2 C25.2 C26.2 C27.2 C28.2 C29.2 C30.2 C31.2 C32.2 C33.2 C34.2 C35.2 C36.2 C37.2 C38.2 C39.2 C40.2 C41.2 C42.2 C43.2 C44.2 C45.2 C46.2 C47.2 C48.2 C49.2 C50.2 C51.2 C52.2 C53.2 C54.2 C55.2 C56.2 C57.2 C58.2 C59.2 C60.2 C61.2 C62.2 C63.2 C64.2 C65.2 C66.2 C67.2 C68.2 C69.2 C70.2 C71.2 C72.2 C73.2 C74.2 C75.2 C76.2 C77.2 C78.2 C79.2 C80.2 C81.2 C82.2 C83.2 C84.2 C85.2 C86.2 C87.2 C88.2 C89.2 C90.2 C91.2 C92.2 C93.2 C94.2 C95.2 C96.2 C97.2 C98.2 C99.2 C100.2 C101.2 C102.2 C103.2 C104.2 C105.2 C106.2 C107.2 C108.2 C109.2 C110.2 C111.2 C112.2 C113.2 C114.2 C115.2 C116.2 C117.2 C118.2 C119.2 C120.2 C121.2 C122.2 C123.2 C124.2 C125.2 C126.2 C127.2 C128.2 C129.2 C130.2 C131.2 C132.2 C133.2 C134.2 C135.2 C136.2 C137.2 C138.2 C139.2 C140.2 C141.2 C142.2 C143.2 C144.2 C145.2 C146.2 C147.2 C148.2 C149.2 C150.2 C151.2 C152.2 C153.2 C154.2 C155.2 C156.2 C157.2 C158.2 C159.2 C160.2 C161.2 C162.2 C163.2 C164.2 C165.2 C166.2 C167.2 C168.2 C169.2 C170.2 C171.2 C172.2 C173.2 C174.2 C175.2 C176.2 C177.2 C178.2 C179.2 C180.2 C181.2 C182.2 C183.2 C184.2 C185.2 C186.2 C187.2 C188.2 C189.2 C190.2 C191.2 C192.2 C193.2 C194.2 C195.2 C196.2 C197.2 C198.2 C199.2 C200.2 C201.2 C202.2 C203.2 C204.2 C205.2 C206.2 C1392.2 C1393.2 C1394.2 C1395.2 C1396.2 C1397.2 C1398.2 C1399.2 R93.2 R95.1 R99.2 R102.1 R103.2 R105.1 R106.1 R107.1 R110.2 R112.2 R113.2 R114.1 R115.1 R116.1 R117.1 R118.1 R120.1 R121.1 R122.1 R124.1 R125.1 R126.1 R127.1 R128.1 R129.1 R133.1 R134.1 R135.1 R136.1 R137.1 R138.1 R140.1 R141.2 R142.1 R143.1 R144.1 R145.1 R146.1 R147.1 R148.1 R149.1 R150.1 R151.1 R152.1 R153.1 R154.1 R155.1 R156.1 R157.1 R158.1 R160.2 R163.2 R164.2 R166.2 R168.2 R171.2 R172.2 R174.2 R176.2 R178.2 R180.2 R182.2 R184.2 R186.2 R188.2 R190.2 R192.2 R194.2 R195.1 R196.1 R197.1 R198.1 R199.1 R200.1 R201.1 R202.1 R203.1 R204.1 R205.1 R206.1 R207.1 R208.1 R209.1 R210.1 R211.1 R212.1 R213.1 R214.1 R215.1 R216.1 R217.1 R218.1 R219.1 R220.1 R221.1 R222.1 R223.1 R224.1 R225.1 R226.1 R227.1 R228.1 R229.1 R230.1 U1.A1(VSS_1) U1.A4(VSS_2) U1.A29(VSS_3) U1.A34(VSS_4) U1.AA3(VSS_177) U1.AA7(VSS_178) U1.AA12(VSS_179) U1.AA14(VSS_180) U1.AA16(VSS_181) U1.AA18(VSS_182) U1.AA22(VSS_183) U1.AA24(VSS_184) U1.AA26(VSS_185) U1.AA28(VSS_186) U1.AA32(VSS_187) U1.AB3(VSS_188) U1.AB6(VSS_189) U1.AB9(VSS_190) U1.AB11(VSS_191) U1.AB13(VSS_192) U1.AB17(VSS_193) U1.AB19(VSS_194) U1.AB21(VSS_195) U1.AB23(VSS_196) U1.AB32(VSS_197) U1.AC3(VSS_198) U1.AC26(VSS_199) U1.AC29(VSS_200) U1.AC32(VSS_201) U1.AD3(VSS_202) U1.AD9(VSS_203) U1.AD11(VSS_204) U1.AD13(VSS_205) U1.AD17(VSS_206) U1.AD22(VSS_207) U1.AD24(VSS_208) U1.AD32(VSS_209) U1.AE3(VSS_210) U1.AE10(VSS_211) U1.AE14(VSS_212) U1.AE18(VSS_213) U1.AE22(VSS_214) U1.AE25(VSS_215) U1.AE32(VSS_216) U1.AF3(VSS_217) U1.AF7(VSS_218) U1.AF28(VSS_219) U1.AF32(VSS_220) U1.AG3(VSS_221) U1.AG7(VSS_222) U1.AG32(VSS_223) U1.AH3(VSS_224) U1.AH10(VSS_225) U1.AH12(VSS_226) U1.AH16(VSS_227) U1.AH20(VSS_228) U1.AH25(VSS_229) U1.AH28(VSS_230) U1.AH29(VSS_231) U1.AH32(VSS_232) U1.AJ3(VSS_233) U1.AJ6(VSS_234) U1.AJ7(VSS_235) U1.AJ12(VSS_236) U1.AJ13(VSS_237) U1.AJ15(VSS_238) U1.AJ19(VSS_239) U1.AJ22(VSS_240) U1.AJ25(VSS_241) U1.AJ28(VSS_242) U1.AJ29(VSS_243) U1.AJ32(VSS_244) U1.AK3(VSS_245) U1.AK6(VSS_246) U1.AK31(VSS_247) U1.AK32(VSS_248) U1.AK33(VSS_249) U1.AK34(VSS_250) U1.AL1(VSS_251) U1.AL2(VSS_252) U1.AL3(VSS_253) U1.AL4(VSS_254) U1.AL5(VSS_255) U1.AL6(VSS_256) U1.AL31(VSS_257) U1.AM3(VSS_258) U1.AM6(VSS_259) U1.AM7(VSS_260) U1.AM8(VSS_261) U1.AM9(VSS_262) U1.AM10(VSS_263) U1.AM11(VSS_264) U1.AM12(VSS_265) U1.AM13(VSS_266) U1.AM14(VSS_267) U1.AM15(VSS_268) U1.AM16(VSS_269) U1.AM17(VSS_270) U1.AM18(VSS_271) U1.AM19(VSS_272) U1.AM20(VSS_273) U1.AM21(VSS_274) U1.AM22(VSS_275) U1.AM23(VSS_276) U1.AM24(VSS_277) U1.AM25(VSS_278) U1.AM26(VSS_279) U1.AM27(VSS_280) U1.AM28(VSS_281) U1.AM29(VSS_282) U1.AM30(VSS_283) U1.AM31(VSS_284) U1.AN1(VSS_285) U1.AN2(VSS_286) U1.AN6(VSS_287) U1.AN31(VSS_288) U1.AP1(VSS_289) U1.AP6(VSS_290) U1.AP31(VSS_291) U1.AP34(VSS_292) U1.B4(VSS_5) U1.B29(VSS_6) U1.C4(VSS_7) U1.C5(VSS_8) U1.C6(VSS_9) U1.C7(VSS_10) U1.C8(VSS_11) U1.C9(VSS_12) U1.C10(VSS_13) U1.C11(VSS_14) U1.C12(VSS_15) U1.C13(VSS_16) U1.C14(VSS_17) U1.C15(VSS_18) U1.C16(VSS_19) U1.C17(VSS_20) U1.C18(VSS_21) U1.C19(VSS_22) U1.C20(VSS_23) U1.C21(VSS_24) U1.C22(VSS_25) U1.C23(VSS_26) U1.C24(VSS_27) U1.C25(VSS_28) U1.C26(VSS_29) U1.C27(VSS_30) U1.C28(VSS_31) U1.C29(VSS_32) U1.D4(VSS_33) U1.D29(VSS_34) U1.D30(VSS_35) U1.D31(VSS_36) U1.D32(VSS_37) U1.D33(VSS_38) U1.D34(VSS_39) U1.E1(VSS_40) U1.E2(VSS_41) U1.E3(VSS_42) U1.E4(VSS_43) U1.E29(VSS_44) U1.E32(VSS_45) U1.F3(VSS_46) U1.F6(VSS_47) U1.F7(VSS_48) U1.F12(VSS_49) U1.F15(VSS_50) U1.F20(VSS_51) U1.F21(VSS_52) U1.F22(VSS_53) U1.F23(VSS_54) U1.F28(VSS_55) U1.F29(VSS_56) U1.F32(VSS_57) U1.G3(VSS_58) U1.G6(VSS_59) U1.G12(VSS_60) U1.G17(VSS_61) U1.G32(VSS_62) U1.H3(VSS_63) U1.H27(VSS_64) U1.H28(VSS_65) U1.H32(VSS_66) U1.J3(VSS_67) U1.J32(VSS_68) U1.K3(VSS_69) U1.K7(VSS_70) U1.K10(VSS_71) U1.K15(VSS_72) U1.K19(VSS_73) U1.K22(VSS_74) U1.K25(VSS_75) U1.K28(VSS_76) U1.K32(VSS_77) U1.L3(VSS_78) U1.L9(VSS_79) U1.L11(VSS_80) U1.L13(VSS_81) U1.L17(VSS_82) U1.L22(VSS_83) U1.L24(VSS_84) U1.L26(VSS_85) U1.L32(VSS_86) U1.M3(VSS_87) U1.M32(VSS_88) U1.N3(VSS_89) U1.N6(VSS_90) U1.N12(VSS_91) U1.N14(VSS_92) U1.N16(VSS_93) U1.N18(VSS_94) U1.N22(VSS_95) U1.N24(VSS_96) U1.N26(VSS_97) U1.N29(VSS_98) U1.N32(VSS_99) U1.P3(VSS_100) U1.P9(VSS_101) U1.P11(VSS_102) U1.P13(VSS_103) U1.P17(VSS_104) U1.P19(VSS_105) U1.P21(VSS_106) U1.P23(VSS_107) U1.P28(VSS_108) U1.P32(VSS_109) U1.R3(VSS_110) U1.R10(VSS_111) U1.R12(VSS_112) U1.R14(VSS_113) U1.R16(VSS_114) U1.R18(VSS_115) U1.R22(VSS_116) U1.R24(VSS_117) U1.R26(VSS_118) U1.R32(VSS_119) U1.T3(VSS_120) U1.T9(VSS_121) U1.T11(VSS_122) U1.T13(VSS_123) U1.T15(VSS_124) U1.T17(VSS_125) U1.T19(VSS_126) U1.T21(VSS_127) U1.T23(VSS_128) U1.T25(VSS_129) U1.T32(VSS_130) U1.U3(VSS_131) U1.U6(VSS_132) U1.U10(VSS_133) U1.U12(VSS_134) U1.U14(VSS_135) U1.U16(VSS_136) U1.U18(VSS_137) U1.U20(VSS_138) U1.U22(VSS_139) U1.U24(VSS_140) U1.U26(VSS_141) U1.U32(VSS_142) U1.V3(VSS_143) U1.V9(VSS_144) U1.V11(VSS_145) U1.V13(VSS_146) U1.V15(VSS_147) U1.V17(VSS_148) U1.V19(VSS_149) U1.V21(VSS_150) U1.V23(VSS_151) U1.V25(VSS_152) U1.V28(VSS_153) U1.V29(VSS_154) U1.V32(VSS_155) U1.W3(VSS_156) U1.W10(VSS_157) U1.W12(VSS_158) U1.W14(VSS_159) U1.W16(VSS_160) U1.W18(VSS_161) U1.W20(VSS_162) U1.W22(VSS_163) U1.W24(VSS_164) U1.W26(VSS_165) U1.W32(VSS_166) U1.Y3(VSS_167) U1.Y9(VSS_168) U1.Y11(VSS_169) U1.Y13(VSS_170) U1.Y17(VSS_171) U1.Y19(VSS_172) U1.Y21(VSS_173) U1.Y23(VSS_174) U1.Y25(VSS_175) U1.Y32(VSS_176) ; also on sheet 3 4 5 6 7 8 9 10 19 20 21 22 23 24 25 26 27 28 29 30 31 32 33 34 35 36 37 38 39 40 41 42 43 44 45 46 47 48 49 50 51 52 53 54 55 56 57 58 59 60 61 62 63 64 65 66 67
P0V9A_PLX1: C128.1 C129.1 C130.1 C131.1 C132.1 C133.1 C134.1 C135.1 C136.1 C137.1 C138.1 C139.1 C140.1 C141.1 C142.1 C143.1 C144.1 C145.1 C146.1 C147.1 C148.1 C149.1 C150.1 C151.1 C152.1 C153.1 C154.1 C155.1 C156.1 C157.1 C158.1 C159.1 C160.1 C161.1 C162.1 C163.1 C164.1 C165.1 C166.1 C167.1 C168.1 C169.1 C170.1 C171.1 C172.1 C173.1 C174.1 C175.1 C176.1 C177.1 C178.1 C179.1 C180.1 C181.1 C182.1 C183.1 C184.1 C185.1 C186.1 C187.1 C188.1 C189.1 C190.1 C191.1 C192.1 C193.1 C194.1 C195.1 C196.1 C197.1 C198.1 C199.1 C200.1 C201.1 C202.1 C203.1 C204.1 C205.1 C206.1 C1396.1 C1397.1 C1398.1 C1399.1 U1.AA10(VDD09A_37) U1.AA15(VDD09A_38) U1.AA20(VDD09A_39) U1.AA25(VDD09A_40) U1.AB10(VDD09A_41) U1.AB15(VDD09A_42) U1.AB20(VDD09A_43) U1.AB25(VDD09A_44) U1.AC10(VDD09A_45) U1.AC11(VDD09A_46) U1.AC12(VDD09A_47) U1.AC13(VDD09A_48) U1.AC14(VDD09A_49) U1.AC15(VDD09A_50) U1.AC16(VDD09A_51) U1.AC17(VDD09A_52) U1.AC18(VDD09A_53) U1.AC19(VDD09A_54) U1.AC20(VDD09A_55) U1.AC21(VDD09A_56) U1.AC22(VDD09A_57) U1.AC23(VDD09A_58) U1.AC24(VDD09A_59) U1.AC25(VDD09A_60) U1.AD10(VDD09A_61) U1.AD14(VDD09A_62) U1.AD16(VDD09A_63) U1.AD19(VDD09A_64) U1.AD21(VDD09A_65) U1.AD25(VDD09A_66) U1.L10(VDD09A_1) U1.L14(VDD09A_2) U1.L16(VDD09A_3) U1.L19(VDD09A_4) U1.L21(VDD09A_5) U1.L25(VDD09A_6) U1.M10(VDD09A_7) U1.M11(VDD09A_8) U1.M12(VDD09A_9) U1.M13(VDD09A_10) U1.M14(VDD09A_11) U1.M15(VDD09A_12) U1.M16(VDD09A_13) U1.M17(VDD09A_14) U1.M18(VDD09A_15) U1.M19(VDD09A_16) U1.M20(VDD09A_17) U1.M21(VDD09A_18) U1.M22(VDD09A_19) U1.M23(VDD09A_20) U1.M24(VDD09A_21) U1.M25(VDD09A_22) U1.N10(VDD09A_23) U1.N15(VDD09A_24) U1.N20(VDD09A_25) U1.N25(VDD09A_26) U1.P10(VDD09A_27) U1.P15(VDD09A_28) U1.P20(VDD09A_29) U1.P25(VDD09A_30) U1.R15(VDD09A_31) U1.R20(VDD09A_32) U1.R25(VDD09A_33) U1.Y10(VDD09A_34) U1.Y15(VDD09A_35) U1.Y20(VDD09A_36) ; also on sheet 51 64
P0V9D_PLX1: C47.1 C48.1 C49.1 C50.1 C51.1 C52.1 C53.1 C54.1 C55.1 C56.1 C57.1 C58.1 C59.1 C60.1 C61.1 C62.1 C63.1 C64.1 C65.1 C66.1 C67.1 C68.1 C69.1 C70.1 C71.1 C72.1 C73.1 C74.1 C75.1 C76.1 C77.1 C78.1 C79.1 C80.1 C81.1 C82.1 C83.1 C84.1 C85.1 C86.1 C87.1 C88.1 C89.1 C90.1 C91.1 C92.1 C93.1 C94.1 C95.1 C96.1 C97.1 C98.1 C99.1 C100.1 C101.1 C102.1 C103.1 C104.1 C105.1 C106.1 C107.1 C108.1 C109.1 C110.1 C111.1 C112.1 C113.1 C114.1 C115.1 C116.1 C117.1 C118.1 C119.1 C120.1 C121.1 C122.1 C123.1 C124.1 C125.1 C126.1 C127.1 C1392.1 C1393.1 C1394.1 C1395.1 U1.AA11(VDD09_57) U1.AA13(VDD09_58) U1.AA17(VDD09_59) U1.AA19(VDD09_60) U1.AA21(VDD09_61) U1.AA23(VDD09_62) U1.AB12(VDD09_63) U1.AB14(VDD09_64) U1.AB16(VDD09_65) U1.AB18(VDD09_66) U1.AB22(VDD09_67) U1.AB24(VDD09_68) U1.N11(VDD09_1) U1.N13(VDD09_2) U1.N17(VDD09_3) U1.N19(VDD09_4) U1.N21(VDD09_5) U1.N23(VDD09_6) U1.P12(VDD09_7) U1.P14(VDD09_8) U1.P16(VDD09_9) U1.P18(VDD09_10) U1.P22(VDD09_11) U1.P24(VDD09_12) U1.R11(VDD09_13) U1.R13(VDD09_14) U1.R17(VDD09_15) U1.R19(VDD09_16) U1.R21(VDD09_17) U1.R23(VDD09_18) U1.T10(VDD09_19) U1.T12(VDD09_20) U1.T14(VDD09_21) U1.T16(VDD09_22) U1.T18(VDD09_23) U1.T20(VDD09_24) U1.T22(VDD09_25) U1.T24(VDD09_26) U1.U11(VDD09_27) U1.U13(VDD09_28) U1.U15(VDD09_29) U1.U17(VDD09_30) U1.U19(VDD09_31) U1.U21(VDD09_32) U1.U23(VDD09_33) U1.U25(VDD09_34) U1.V10(VDD09_35) U1.V12(VDD09_36) U1.V14(VDD09_37) U1.V16(VDD09_38) U1.V18(VDD09_39) U1.V20(VDD09_40) U1.V22(VDD09_41) U1.V24(VDD09_42) U1.W11(VDD09_43) U1.W13(VDD09_44) U1.W15(VDD09_45) U1.W17(VDD09_46) U1.W19(VDD09_47) U1.W21(VDD09_48) U1.W23(VDD09_49) U1.W25(VDD09_50) U1.Y12(VDD09_52) U1.Y14(VDD09_51) U1.Y16(VDD09_53) U1.Y18(VDD09_54) U1.Y22(VDD09_55) U1.Y24(VDD09_56) ; also on sheet 51 62
P1V8A_PLX1: C25.1 C26.1 C27.1 C28.1 C29.1 C30.1 C31.1 C32.1 C33.1 C34.1 C35.1 C36.1 C37.1 C38.1 C39.1 C40.1 C41.1 C42.1 C43.1 C44.1 C45.1 C46.1 U1.AA9(VDD18A_8) U1.AB26(VDD18A_9) U1.AD12(VDD18A_10) U1.AD15(VDD18A_11) U1.AD18(VDD18A_12) U1.AD20(VDD18A_13) U1.AD23(VDD18A_14) U1.L12(VDD18A_1) U1.L15(VDD18A_2) U1.L18(VDD18A_3) U1.L20(VDD18A_4) U1.L23(VDD18A_5) U1.N9(VDD18A_6) U1.P26(VDD18A_7) ; also on sheet 9 60
P1V8D_PLX1: C3.1 C4.1 C5.1 C6.1 C7.1 C8.1 C9.1 C10.1 C11.1 C12.1 C13.1 C14.1 C15.1 C16.1 C17.1 C18.1 C19.1 C20.1 C21.1 C22.1 C23.1 C24.1 R91.2 R92.1 R94.2 R96.2 R97.2 R98.2 R100.1 R101.2 R104.1 R108.1 R109.2 R111.1 R119.2 R123.2 R130.1 R131.1 R132.1 R139.2 R159.2 R161.2 R162.2 R165.2 R167.2 R169.2 R170.2 R173.2 R175.2 R177.2 R179.2 R181.2 R183.2 R185.2 R187.2 R189.2 R191.2 R193.2 U1.AG8(VDD18_11) U1.AG15(VDD18_12) U1.AG22(VDD18_13) U1.AG28(VDD18_14) U1.J9(VDD18_1) U1.J15(VDD18_2) U1.J21(VDD18_3) U1.J26(VDD18_4) U1.R9(VDD18_5) U1.T26(VDD18_6) U1.U9(VDD18_7) U1.V26(VDD18_8) U1.W9(VDD18_9) U1.Y26(VDD18_10) ; also on sheet 9 10 46 51 60
CLK_100M_PLX2_PEXREF_N: U3.AM1(PEX_REFCLKN) ; also on sheet 28
CLK_100M_PLX2_PEXREF_P: U3.AM2(PEX_REFCLKP) ; also on sheet 28
PEX_IPASS_B_RXN0: U3.AL10(PEX_PERN15) ; also on sheet 30
PEX_IPASS_B_RXN1: U3.AL9(PEX_PERN14) ; also on sheet 30
PEX_IPASS_B_RXN2: U3.AL8(PEX_PERN13) ; also on sheet 30
PEX_IPASS_B_RXN3: U3.AL7(PEX_PERN12) ; also on sheet 30
PEX_IPASS_B_RXN4: U3.AK4(PEX_PERN11) ; also on sheet 30
PEX_IPASS_B_RXN5: U3.AJ4(PEX_PERN10) ; also on sheet 30
PEX_IPASS_B_RXN6: U3.AH4(PEX_PERN9) ; also on sheet 30
PEX_IPASS_B_RXN7: U3.AG4(PEX_PERN8) ; also on sheet 30
PEX_IPASS_B_RXN8: U3.AF4(PEX_PERN7) ; also on sheet 30
PEX_IPASS_B_RXN9: U3.AE4(PEX_PERN6) ; also on sheet 30
PEX_IPASS_B_RXN10: U3.AD4(PEX_PERN5) ; also on sheet 30
PEX_IPASS_B_RXN11: U3.AC4(PEX_PERN4) ; also on sheet 30
PEX_IPASS_B_RXN12: U3.AA4(PEX_PERN3) ; also on sheet 30
PEX_IPASS_B_RXN13: U3.Y4(PEX_PERN2) ; also on sheet 30
PEX_IPASS_B_RXN14: U3.W4(PEX_PERN1) ; also on sheet 30
PEX_IPASS_B_RXN15: U3.V4(PEX_PERN0) ; also on sheet 30
PEX_IPASS_B_RXP0: U3.AK10(PEX_PERP15) ; also on sheet 30
PEX_IPASS_B_RXP1: U3.AK9(PEX_PERP14) ; also on sheet 30
PEX_IPASS_B_RXP2: U3.AK8(PEX_PERP13) ; also on sheet 30
PEX_IPASS_B_RXP3: U3.AK7(PEX_PERP12) ; also on sheet 30
PEX_IPASS_B_RXP4: U3.AK5(PEX_PERP11) ; also on sheet 30
PEX_IPASS_B_RXP5: U3.AJ5(PEX_PERP10) ; also on sheet 30
PEX_IPASS_B_RXP6: U3.AH5(PEX_PERP9) ; also on sheet 30
PEX_IPASS_B_RXP7: U3.AG5(PEX_PERP8) ; also on sheet 30
PEX_IPASS_B_RXP8: U3.AF5(PEX_PERP7) ; also on sheet 30
PEX_IPASS_B_RXP9: U3.AE5(PEX_PERP6) ; also on sheet 30
PEX_IPASS_B_RXP10: U3.AD5(PEX_PERP5) ; also on sheet 30
PEX_IPASS_B_RXP11: U3.AC5(PEX_PERP4) ; also on sheet 30
PEX_IPASS_B_RXP12: U3.AA5(PEX_PERP3) ; also on sheet 30
PEX_IPASS_B_RXP13: U3.Y5(PEX_PERP2) ; also on sheet 30
PEX_IPASS_B_RXP14: U3.W5(PEX_PERP1) ; also on sheet 30
PEX_IPASS_B_RXP15: U3.V5(PEX_PERP0) ; also on sheet 30
PEX_IPASS_B_TXN0: U3.AP10(PEX_PETN15) ; also on sheet 30
PEX_IPASS_B_TXN1: U3.AP9(PEX_PETN14) ; also on sheet 30
PEX_IPASS_B_TXN2: U3.AP8(PEX_PETN13) ; also on sheet 30
PEX_IPASS_B_TXN3: U3.AP7(PEX_PETN12) ; also on sheet 30
PEX_IPASS_B_TXN4: U3.AK1(PEX_PETN11) ; also on sheet 30
PEX_IPASS_B_TXN5: U3.AJ1(PEX_PETN10) ; also on sheet 30
PEX_IPASS_B_TXN6: U3.AH1(PEX_PETN9) ; also on sheet 30
PEX_IPASS_B_TXN7: U3.AG1(PEX_PETN8) ; also on sheet 30
PEX_IPASS_B_TXN8: U3.AF1(PEX_PETN7) ; also on sheet 30
PEX_IPASS_B_TXN9: U3.AE1(PEX_PETN6) ; also on sheet 30
PEX_IPASS_B_TXN10: U3.AD1(PEX_PETN5) ; also on sheet 30
PEX_IPASS_B_TXN11: U3.AC1(PEX_PETN4) ; also on sheet 30
PEX_IPASS_B_TXN12: U3.AA1(PEX_PETN3) ; also on sheet 30
PEX_IPASS_B_TXN13: U3.Y1(PEX_PETN2) ; also on sheet 30
PEX_IPASS_B_TXN14: U3.W1(PEX_PETN1) ; also on sheet 30
PEX_IPASS_B_TXN15: U3.V1(PEX_PETN0) ; also on sheet 30
PEX_IPASS_B_TXP0: U3.AN10(PEX_PETP15) ; also on sheet 30
PEX_IPASS_B_TXP1: U3.AN9(PEX_PETP14) ; also on sheet 30
PEX_IPASS_B_TXP2: U3.AN8(PEX_PETP13) ; also on sheet 30
PEX_IPASS_B_TXP3: U3.AN7(PEX_PETP12) ; also on sheet 30
PEX_IPASS_B_TXP4: U3.AK2(PEX_PETP11) ; also on sheet 30
PEX_IPASS_B_TXP5: U3.AJ2(PEX_PETP10) ; also on sheet 30
PEX_IPASS_B_TXP6: U3.AH2(PEX_PETP9) ; also on sheet 30
PEX_IPASS_B_TXP7: U3.AG2(PEX_PETP8) ; also on sheet 30
PEX_IPASS_B_TXP8: U3.AF2(PEX_PETP7) ; also on sheet 30
PEX_IPASS_B_TXP9: U3.AE2(PEX_PETP6) ; also on sheet 30
PEX_IPASS_B_TXP10: U3.AD2(PEX_PETP5) ; also on sheet 30
PEX_IPASS_B_TXP11: U3.AC2(PEX_PETP4) ; also on sheet 30
PEX_IPASS_B_TXP12: U3.AA2(PEX_PETP3) ; also on sheet 30
PEX_IPASS_B_TXP13: U3.Y2(PEX_PETP2) ; also on sheet 30
PEX_IPASS_B_TXP14: U3.W2(PEX_PETP1) ; also on sheet 30
PEX_IPASS_B_TXP15: U3.V2(PEX_PETP0) ; also on sheet 30
PEX_NIC3_RXN0: U3.D8(PEX_PERN16) ; also on sheet 40
PEX_NIC3_RXN1: U3.D7(PEX_PERN17) ; also on sheet 40
PEX_NIC3_RXN2: U3.D6(PEX_PERN18) ; also on sheet 40
PEX_NIC3_RXN3: U3.D5(PEX_PERN19) ; also on sheet 40
PEX_NIC3_RXN4: U3.F4(PEX_PERN20) ; also on sheet 40
PEX_NIC3_RXN5: U3.G4(PEX_PERN21) ; also on sheet 40
PEX_NIC3_RXN6: U3.H4(PEX_PERN22) ; also on sheet 40
PEX_NIC3_RXN7: U3.J4(PEX_PERN23) ; also on sheet 40
PEX_NIC3_RXP0: U3.E8(PEX_PERP16) ; also on sheet 40
PEX_NIC3_RXP1: U3.E7(PEX_PERP17) ; also on sheet 40
PEX_NIC3_RXP2: U3.E6(PEX_PERP18) ; also on sheet 40
PEX_NIC3_RXP3: U3.E5(PEX_PERP19) ; also on sheet 40
PEX_NIC3_RXP4: U3.F5(PEX_PERP20) ; also on sheet 40
PEX_NIC3_RXP5: U3.G5(PEX_PERP21) ; also on sheet 40
PEX_NIC3_RXP6: U3.H5(PEX_PERP22) ; also on sheet 40
PEX_NIC3_RXP7: U3.J5(PEX_PERP23) ; also on sheet 40
PEX_NIC3_TXN0: U3.A8(PEX_PETN16) ; also on sheet 40
PEX_NIC3_TXN1: U3.A7(PEX_PETN17) ; also on sheet 40
PEX_NIC3_TXN2: U3.A6(PEX_PETN18) ; also on sheet 40
PEX_NIC3_TXN3: U3.A5(PEX_PETN19) ; also on sheet 40
PEX_NIC3_TXN4: U3.F1(PEX_PETN20) ; also on sheet 40
PEX_NIC3_TXN5: U3.G1(PEX_PETN21) ; also on sheet 40
PEX_NIC3_TXN6: U3.H1(PEX_PETN22) ; also on sheet 40
PEX_NIC3_TXN7: U3.J1(PEX_PETN23) ; also on sheet 40
PEX_NIC3_TXP0: U3.B8(PEX_PETP16) ; also on sheet 40
PEX_NIC3_TXP1: U3.B7(PEX_PETP17) ; also on sheet 40
PEX_NIC3_TXP2: U3.B6(PEX_PETP18) ; also on sheet 40
PEX_NIC3_TXP3: U3.B5(PEX_PETP19) ; also on sheet 40
PEX_NIC3_TXP4: U3.F2(PEX_PETP20) ; also on sheet 40
PEX_NIC3_TXP5: U3.G2(PEX_PETP21) ; also on sheet 40
PEX_NIC3_TXP6: U3.H2(PEX_PETP22) ; also on sheet 40
PEX_NIC3_TXP7: U3.J2(PEX_PETP23) ; also on sheet 40
PEX_NIC4_RXN8: U3.K4(PEX_PERN24) ; also on sheet 40
PEX_NIC4_RXN9: U3.L4(PEX_PERN25) ; also on sheet 40
PEX_NIC4_RXN10: U3.M4(PEX_PERN26) ; also on sheet 40
PEX_NIC4_RXN11: U3.N4(PEX_PERN27) ; also on sheet 40
PEX_NIC4_RXN12: U3.P4(PEX_PERN28) ; also on sheet 40
PEX_NIC4_RXN13: U3.R4(PEX_PERN29) ; also on sheet 40
PEX_NIC4_RXN14: U3.T4(PEX_PERN30) ; also on sheet 40
PEX_NIC4_RXN15: U3.U4(PEX_PERN31) ; also on sheet 40
PEX_NIC4_RXP8: U3.K5(PEX_PERP24) ; also on sheet 40
PEX_NIC4_RXP9: U3.L5(PEX_PERP25) ; also on sheet 40
PEX_NIC4_RXP10: U3.M5(PEX_PERP26) ; also on sheet 40
PEX_NIC4_RXP11: U3.N5(PEX_PERP27) ; also on sheet 40
PEX_NIC4_RXP12: U3.P5(PEX_PERP28) ; also on sheet 40
PEX_NIC4_RXP13: U3.R5(PEX_PERP29) ; also on sheet 40
PEX_NIC4_RXP14: U3.T5(PEX_PERP30) ; also on sheet 40
PEX_NIC4_RXP15: U3.U5(PEX_PERP31) ; also on sheet 40
PEX_NIC4_TXN8: U3.K1(PEX_PETN24) ; also on sheet 40
PEX_NIC4_TXN9: U3.L1(PEX_PETN25) ; also on sheet 40
PEX_NIC4_TXN10: U3.M1(PEX_PETN26) ; also on sheet 40
PEX_NIC4_TXN11: U3.N1(PEX_PETN27) ; also on sheet 40
PEX_NIC4_TXN12: U3.P1(PEX_PETN28) ; also on sheet 40
PEX_NIC4_TXN13: U3.R1(PEX_PETN29) ; also on sheet 40
PEX_NIC4_TXN14: U3.T1(PEX_PETN30) ; also on sheet 40
PEX_NIC4_TXN15: U3.U1(PEX_PETN31) ; also on sheet 40
PEX_NIC4_TXP8: U3.K2(PEX_PETP24) ; also on sheet 40
PEX_NIC4_TXP9: U3.L2(PEX_PETP25) ; also on sheet 40
PEX_NIC4_TXP10: U3.M2(PEX_PETP26) ; also on sheet 40
PEX_NIC4_TXP11: U3.N2(PEX_PETP27) ; also on sheet 40
PEX_NIC4_TXP12: U3.P2(PEX_PETP28) ; also on sheet 40
PEX_NIC4_TXP13: U3.R2(PEX_PETP29) ; also on sheet 40
PEX_NIC4_TXP14: U3.T2(PEX_PETP30) ; also on sheet 40
PEX_NIC4_TXP15: U3.U2(PEX_PETP31) ; also on sheet 40
PEX_PE4_RXN0: U3.AL26(PEX_PERN47) ; also on sheet 35
PEX_PE4_RXN1: U3.AL25(PEX_PERN46) ; also on sheet 35
PEX_PE4_RXN2: U3.AL24(PEX_PERN45) ; also on sheet 35
PEX_PE4_RXN3: U3.AL23(PEX_PERN44) ; also on sheet 35
PEX_PE4_RXN4: U3.AL22(PEX_PERN43) ; also on sheet 35
PEX_PE4_RXN5: U3.AL21(PEX_PERN42) ; also on sheet 35
PEX_PE4_RXN6: U3.AL20(PEX_PERN41) ; also on sheet 35
PEX_PE4_RXN7: U3.AL19(PEX_PERN40) ; also on sheet 35
PEX_PE4_RXN8: U3.AL18(PEX_PERN39) ; also on sheet 35
PEX_PE4_RXN9: U3.AL17(PEX_PERN38) ; also on sheet 35
PEX_PE4_RXN10: U3.AL16(PEX_PERN37) ; also on sheet 35
PEX_PE4_RXN11: U3.AL15(PEX_PERN36) ; also on sheet 35
PEX_PE4_RXN12: U3.AL14(PEX_PERN35) ; also on sheet 35
PEX_PE4_RXN13: U3.AL13(PEX_PERN34) ; also on sheet 35
PEX_PE4_RXN14: U3.AL12(PEX_PERN33) ; also on sheet 35
PEX_PE4_RXN15: U3.AL11(PEX_PERN32) ; also on sheet 35
PEX_PE4_RXP0: U3.AK26(PEX_PERP47) ; also on sheet 35
PEX_PE4_RXP1: U3.AK25(PEX_PERP46) ; also on sheet 35
PEX_PE4_RXP2: U3.AK24(PEX_PERP45) ; also on sheet 35
PEX_PE4_RXP3: U3.AK23(PEX_PERP44) ; also on sheet 35
PEX_PE4_RXP4: U3.AK22(PEX_PERP43) ; also on sheet 35
PEX_PE4_RXP5: U3.AK21(PEX_PERP42) ; also on sheet 35
PEX_PE4_RXP6: U3.AK20(PEX_PERP41) ; also on sheet 35
PEX_PE4_RXP7: U3.AK19(PEX_PERP40) ; also on sheet 35
PEX_PE4_RXP8: U3.AK18(PEX_PERP39) ; also on sheet 35
PEX_PE4_RXP9: U3.AK17(PEX_PERP38) ; also on sheet 35
PEX_PE4_RXP10: U3.AK16(PEX_PERP37) ; also on sheet 35
PEX_PE4_RXP11: U3.AK15(PEX_PERP36) ; also on sheet 35
PEX_PE4_RXP12: U3.AK14(PEX_PERP35) ; also on sheet 35
PEX_PE4_RXP13: U3.AK13(PEX_PERP34) ; also on sheet 35
PEX_PE4_RXP14: U3.AK12(PEX_PERP33) ; also on sheet 35
PEX_PE4_RXP15: U3.AK11(PEX_PERP32) ; also on sheet 35
PEX_PE4_TXN0: U3.AP26(PEX_PETN47) ; also on sheet 35
PEX_PE4_TXN1: U3.AP25(PEX_PETN46) ; also on sheet 35
PEX_PE4_TXN2: U3.AP24(PEX_PETN45) ; also on sheet 35
PEX_PE4_TXN3: U3.AP23(PEX_PETN44) ; also on sheet 35
PEX_PE4_TXN4: U3.AP22(PEX_PETN43) ; also on sheet 35
PEX_PE4_TXN5: U3.AP21(PEX_PETN42) ; also on sheet 35
PEX_PE4_TXN6: U3.AP20(PEX_PETN41) ; also on sheet 35
PEX_PE4_TXN7: U3.AP19(PEX_PETN40) ; also on sheet 35
PEX_PE4_TXN8: U3.AP18(PEX_PETN39) ; also on sheet 35
PEX_PE4_TXN9: U3.AP17(PEX_PETN38) ; also on sheet 35
PEX_PE4_TXN10: U3.AP16(PEX_PETN37) ; also on sheet 35
PEX_PE4_TXN11: U3.AP15(PEX_PETN36) ; also on sheet 35
PEX_PE4_TXN12: U3.AP14(PEX_PETN35) ; also on sheet 35
PEX_PE4_TXN13: U3.AP13(PEX_PETN34) ; also on sheet 35
PEX_PE4_TXN14: U3.AP12(PEX_PETN33) ; also on sheet 35
PEX_PE4_TXN15: U3.AP11(PEX_PETN32) ; also on sheet 35
PEX_PE4_TXP0: U3.AN26(PEX_PETP47) ; also on sheet 35
PEX_PE4_TXP1: U3.AN25(PEX_PETP46) ; also on sheet 35
PEX_PE4_TXP2: U3.AN24(PEX_PETP45) ; also on sheet 35
PEX_PE4_TXP3: U3.AN23(PEX_PETP44) ; also on sheet 35
PEX_PE4_TXP4: U3.AN22(PEX_PETP43) ; also on sheet 35
PEX_PE4_TXP5: U3.AN21(PEX_PETP42) ; also on sheet 35
PEX_PE4_TXP6: U3.AN20(PEX_PETP41) ; also on sheet 35
PEX_PE4_TXP7: U3.AN19(PEX_PETP40) ; also on sheet 35
PEX_PE4_TXP8: U3.AN18(PEX_PETP39) ; also on sheet 35
PEX_PE4_TXP9: U3.AN17(PEX_PETP38) ; also on sheet 35
PEX_PE4_TXP10: U3.AN16(PEX_PETP37) ; also on sheet 35
PEX_PE4_TXP11: U3.AN15(PEX_PETP36) ; also on sheet 35
PEX_PE4_TXP12: U3.AN14(PEX_PETP35) ; also on sheet 35
PEX_PE4_TXP13: U3.AN13(PEX_PETP34) ; also on sheet 35
PEX_PE4_TXP14: U3.AN12(PEX_PETP33) ; also on sheet 35
PEX_PE4_TXP15: U3.AN11(PEX_PETP32) ; also on sheet 35
PEX_PE7_RXN0: U3.D9(PEX_PERN63) ; also on sheet 38
PEX_PE7_RXN1: U3.D10(PEX_PERN62) ; also on sheet 38
PEX_PE7_RXN2: U3.D11(PEX_PERN61) ; also on sheet 38
PEX_PE7_RXN3: U3.D12(PEX_PERN60) ; also on sheet 38
PEX_PE7_RXN4: U3.D13(PEX_PERN59) ; also on sheet 38
PEX_PE7_RXN5: U3.D14(PEX_PERN58) ; also on sheet 38
PEX_PE7_RXN6: U3.D15(PEX_PERN57) ; also on sheet 38
PEX_PE7_RXN7: U3.D16(PEX_PERN56) ; also on sheet 38
PEX_PE7_RXN8: U3.D17(PEX_PERN55) ; also on sheet 38
PEX_PE7_RXN9: U3.D18(PEX_PERN54) ; also on sheet 38
PEX_PE7_RXN10: U3.D19(PEX_PERN53) ; also on sheet 38
PEX_PE7_RXN11: U3.D20(PEX_PERN52) ; also on sheet 38
PEX_PE7_RXN12: U3.D21(PEX_PERN51) ; also on sheet 38
PEX_PE7_RXN13: U3.D22(PEX_PERN50) ; also on sheet 38
PEX_PE7_RXN14: U3.D23(PEX_PERN49) ; also on sheet 38
PEX_PE7_RXN15: U3.D24(PEX_PERN48) ; also on sheet 38
PEX_PE7_RXP0: U3.E9(PEX_PERP63) ; also on sheet 38
PEX_PE7_RXP1: U3.E10(PEX_PERP62) ; also on sheet 38
PEX_PE7_RXP2: U3.E11(PEX_PERP61) ; also on sheet 38
PEX_PE7_RXP3: U3.E12(PEX_PERP60) ; also on sheet 38
PEX_PE7_RXP4: U3.E13(PEX_PERP59) ; also on sheet 38
PEX_PE7_RXP5: U3.E14(PEX_PERP58) ; also on sheet 38
PEX_PE7_RXP6: U3.E15(PEX_PERP57) ; also on sheet 38
PEX_PE7_RXP7: U3.E16(PEX_PERP56) ; also on sheet 38
PEX_PE7_RXP8: U3.E17(PEX_PERP55) ; also on sheet 38
PEX_PE7_RXP9: U3.E18(PEX_PERP54) ; also on sheet 38
PEX_PE7_RXP10: U3.E19(PEX_PERP53) ; also on sheet 38
PEX_PE7_RXP11: U3.E20(PEX_PERP52) ; also on sheet 38
PEX_PE7_RXP12: U3.E21(PEX_PERP51) ; also on sheet 38
PEX_PE7_RXP13: U3.E22(PEX_PERP50) ; also on sheet 38
PEX_PE7_RXP14: U3.E23(PEX_PERP49) ; also on sheet 38
PEX_PE7_RXP15: U3.E24(PEX_PERP48) ; also on sheet 38
PEX_PE7_TXN0: U3.A9(PEX_PETN63) ; also on sheet 38
PEX_PE7_TXN1: U3.A10(PEX_PETN62) ; also on sheet 38
PEX_PE7_TXN2: U3.A11(PEX_PETN61) ; also on sheet 38
PEX_PE7_TXN3: U3.A12(PEX_PETN60) ; also on sheet 38
PEX_PE7_TXN4: U3.A13(PEX_PETN59) ; also on sheet 38
PEX_PE7_TXN5: U3.A14(PEX_PETN58) ; also on sheet 38
PEX_PE7_TXN6: U3.A15(PEX_PETN57) ; also on sheet 38
PEX_PE7_TXN7: U3.A16(PEX_PETN56) ; also on sheet 38
PEX_PE7_TXN8: U3.A17(PEX_PETN55) ; also on sheet 38
PEX_PE7_TXN9: U3.A18(PEX_PETN54) ; also on sheet 38
PEX_PE7_TXN10: U3.A19(PEX_PETN53) ; also on sheet 38
PEX_PE7_TXN11: U3.A20(PEX_PETN52) ; also on sheet 38
PEX_PE7_TXN12: U3.A21(PEX_PETN51) ; also on sheet 38
PEX_PE7_TXN13: U3.A22(PEX_PETN50) ; also on sheet 38
PEX_PE7_TXN14: U3.A23(PEX_PETN49) ; also on sheet 38
PEX_PE7_TXN15: U3.A24(PEX_PETN48) ; also on sheet 38
PEX_PE7_TXP0: U3.B9(PEX_PETP63) ; also on sheet 38
PEX_PE7_TXP1: U3.B10(PEX_PETP62) ; also on sheet 38
PEX_PE7_TXP2: U3.B11(PEX_PETP61) ; also on sheet 38
PEX_PE7_TXP3: U3.B12(PEX_PETP60) ; also on sheet 38
PEX_PE7_TXP4: U3.B13(PEX_PETP59) ; also on sheet 38
PEX_PE7_TXP5: U3.B14(PEX_PETP58) ; also on sheet 38
PEX_PE7_TXP6: U3.B15(PEX_PETP57) ; also on sheet 38
PEX_PE7_TXP7: U3.B16(PEX_PETP56) ; also on sheet 38
PEX_PE7_TXP8: U3.B17(PEX_PETP55) ; also on sheet 38
PEX_PE7_TXP9: U3.B18(PEX_PETP54) ; also on sheet 38
PEX_PE7_TXP10: U3.B19(PEX_PETP53) ; also on sheet 38
PEX_PE7_TXP11: U3.B20(PEX_PETP52) ; also on sheet 38
PEX_PE7_TXP12: U3.B21(PEX_PETP51) ; also on sheet 38
PEX_PE7_TXP13: U3.B22(PEX_PETP50) ; also on sheet 38
PEX_PE7_TXP14: U3.B23(PEX_PETP49) ; also on sheet 38
PEX_PE7_TXP15: U3.B24(PEX_PETP48) ; also on sheet 38
PLX2_REXT_A0: R196.2 U3.W6(REXT_A0)
PLX2_REXT_A1: R197.2 U3.AE6(REXT_A1)
PLX2_REXT_A2: R199.2 U3.AH6(REXT_A2)
PLX2_REXT_A3: R201.2 U3.AJ9(REXT_A3)
PLX2_REXT_A4: R204.2 U3.F9(REXT_A4)
PLX2_REXT_A5: R206.2 U3.H6(REXT_A5)
PLX2_REXT_A6: R209.2 U3.L6(REXT_A6)
PLX2_REXT_A7: R211.2 U3.T6(REXT_A7)
PLX2_REXT_A8: R213.2 U3.AJ11(REXT_A8)
PLX2_REXT_A9: R217.2 U3.AJ17(REXT_A9)
PLX2_REXT_A10: R214.2 U3.AJ21(REXT_A10)
PLX2_REXT_A11: R219.2 U3.AJ24(REXT_A11)
PLX2_REXT_A12: R224.2 U3.F25(REXT_A12)
PLX2_REXT_A13: R222.2 U3.F19(REXT_A13)
PLX2_REXT_A14: R226.2 U3.F14(REXT_A14)
PLX2_REXT_A15: R228.2 U3.F11(REXT_A15)
PLX2_REXT_B0: R195.2 U3.V6(REXT_B0)
PLX2_REXT_B1: R198.2 U3.AD6(REXT_B1)
PLX2_REXT_B2: R200.2 U3.AG6(REXT_B2)
PLX2_REXT_B3: R202.2 U3.AJ8(REXT_B3)
PLX2_REXT_B4: R205.2 U3.F8(REXT_B4)
PLX2_REXT_B5: R208.2 U3.J6(REXT_B5)
PLX2_REXT_B6: R210.2 U3.M6(REXT_B6)
PLX2_REXT_B7: R212.2 U3.R6(REXT_B7)
PLX2_REXT_B8: R216.2 U3.AJ10(REXT_B8)
PLX2_REXT_B9: R218.2 U3.AJ16(REXT_B9)
PLX2_REXT_B10: R215.2 U3.AJ20(REXT_B10)
PLX2_REXT_B11: R220.2 U3.AJ23(REXT_B11)
PLX2_REXT_B12: R225.2 U3.F24(REXT_B12)
PLX2_REXT_B13: R223.2 U3.F18(REXT_B13)
PLX2_REXT_B14: R227.2 U3.F13(REXT_B14)
PLX2_REXT_B15: R229.2 U3.F10(REXT_B15)
PLX2_REXT_CMU0: R203.2 U3.AF6(REXT_CMU0)
PLX2_REXT_CMU1: R207.2 U3.K6(REXT_CMU1)
PLX2_REXT_CMU2: R221.2 U3.AJ18(REXT_CMU2)
PLX2_REXT_CMU3: R230.2 U3.F16(REXT_CMU3)
PLX_STRAP_GEN1_COMPLIANCE_N: R104.2 U1.K8(STRAP_GEN1_COMPLIANCE#)
PLX_STRAP_GEN1_GEN2: R183.1 R184.1 U1.H17(STRAP_GEN1_GEN2)
PLX_STRAP_HP_POLARITY_CTRL: R108.2 U1.AE15(STRAP_HP_POLARITY_CTRL)
PLX_STRAP_I2C_SMBUS_CFG_EN_N: R111.2 U1.AN3(STRAP_I2C_SMBUS_CFG_EN#)
PLX_STRAP_I2C_SMBUS_SEL: R189.1 R190.1 U1.AP4(STRAP_I2C_SMBUS_SEL)
PLX_STRAP_MGMT_CFG_EN: R170.1 R172.1 U1.V8(STRAP_MGMT_CFG_EN)
PLX_STRAP_NT0_UPSTRM_PORTSEL0: R91.1 R93.1 U1.N7(STRAP_NT0_UPSTRM_PORTSEL0)
PLX_STRAP_NT0_UPSTRM_PORTSEL1: R97.1 R99.1 U1.C2(STRAP_NT0_UPSTRM_PORTSEL1)
PLX_STRAP_NT0_UPSTRM_PORTSEL2: R101.1 R103.1 U1.AN5(STRAP_NT0_UPSTRM_PORTSEL2)
PLX_STRAP_NT1_UPSTRM_PORTSEL0: R109.1 R110.1 U1.K16(STRAP_NT1_UPSTRM_PORTSEL0)
PLX_STRAP_NT1_UPSTRM_PORTSEL1: R112.1 R119.1 U1.J13(STRAP_NT1_UPSTRM_PORTSEL1)
PLX_STRAP_NT1_UPSTRM_PORTSEL2: R113.1 R123.1 U1.G15(STRAP_NT1_UPSTRM_PORTSEL2)
PLX_STRAP_PLL_BYPASS_N: R130.2 U1.AF15(STRAP_PLL_BYPASS#)
PLX_STRAP_PROBE_MODE_N: R131.2 U1.AE17(STRAP_PROBE_MODE#)
PLX_STRAP_REFCLK_SSC_EN0: R133.2 U1.AH13(STRAP_REFCLK_SSC_EN0)
PLX_STRAP_REFCLK_SSC_EN1: R134.2 U1.W8(STRAP_REFCLK_SSC_EN1)
PLX_STRAP_REFCLK_SSC_EN2: R135.2 U1.AG19(STRAP_REFCLK_SSC_EN2)
PLX_STRAP_REFCLK_SSC_EN3: R136.2 U1.AH19(STRAP_REFCLK_SSC_EN3)
PLX_STRAP_REFCLK_SSC_EN4: R137.2 U1.M9(STRAP_REFCLK_SSC_EN4)
PLX_STRAP_REFCLK_SSC_EN5: R138.2 U1.G16(STRAP_REFCLK_SSC_EN5)
PLX_STRAP_REFCLK_SSC_EN6: R140.2 U1.P8(STRAP_REFCLK_SSC_EN6)
PLX_STRAP_REFCLK_SSC_EN7: R142.2 U1.C1(STRAP_REFCLK_SSC_EN7)
PLX_STRAP_REFCLK_SSC_EN8: R143.2 U1.AE26(STRAP_REFCLK_SSC_EN8)
PLX_STRAP_REFCLK_SSC_EN9: R144.2 U1.AG20(STRAP_REFCLK_SSC_EN9)
PLX_STRAP_REFCLK_SSC_EN10: R145.2 U1.AP32(STRAP_REFCLK_SSC_EN10)
PLX_STRAP_REFCLK_SSC_EN11: R146.2 U1.AL33(STRAP_REFCLK_SSC_EN11)
PLX_STRAP_REFCLK_SSC_EN12: R147.2 U1.J20(STRAP_REFCLK_SSC_EN12)
PLX_STRAP_REFCLK_SSC_EN13: R148.2 U1.J24(STRAP_REFCLK_SSC_EN13)
PLX_STRAP_REFCLK_SSC_EN14: R149.2 U1.G21(STRAP_REFCLK_SSC_EN14)
PLX_STRAP_REFCLK_SSC_EN15: R150.2 U1.H21(STRAP_REFCLK_SSC_EN15)
PLX_STRAP_REFCLK_SSC_EN16: R151.2 U1.Y28(STRAP_REFCLK_SSC_EN16)
PLX_STRAP_REFCLK_SSC_EN17: R152.2 U1.AP33(STRAP_REFCLK_SSC_EN17)
PLX_STRAP_REFCLK_SSC_EN18: R153.2 U1.V27(STRAP_REFCLK_SSC_EN18)
PLX_STRAP_REFCLK_SSC_EN19: R154.2 U1.U28(STRAP_REFCLK_SSC_EN19)
PLX_STRAP_REFCLK_SSC_EN20: R155.2 U1.J27(STRAP_REFCLK_SSC_EN20)
PLX_STRAP_REFCLK_SSC_EN21: R156.2 U1.M28(STRAP_REFCLK_SSC_EN21)
PLX_STRAP_REFCLK_SSC_EN22: R157.2 U1.C32(STRAP_REFCLK_SSC_EN22)
PLX_STRAP_REFCLK_SSC_EN23: R158.2 U1.B31(STRAP_REFCLK_SSC_EN23)
PLX_STRAP_RESERVED0: R94.1 R105.2 U1.AM4(STRAP_RESERVED0)
PLX_STRAP_RESERVED1: R106.2 U1.AC8(STRAP_RESERVED1)
PLX_STRAP_RESERVED2: R96.1 R114.2 U1.H8(STRAP_RESERVED2)
PLX_STRAP_RESERVED3: R107.2 U1.AF12(STRAP_RESERVED3)
PLX_STRAP_RESERVED4: R115.2 U1.M7(STRAP_RESERVED4)
PLX_STRAP_RESERVED5: R116.2 U1.G9(STRAP_RESERVED5)
PLX_STRAP_RESERVED6: R117.2 U1.AP5(STRAP_RESERVED6)
PLX_STRAP_RESERVED7: R118.2 U1.AC9(STRAP_RESERVED7)
PLX_STRAP_RESERVED8: R120.2 U1.AF19(STRAP_RESERVED8)
PLX_STRAP_RESERVED9: R121.2 U1.AH18(STRAP_RESERVED9)
PLX_STRAP_RESERVED10: R98.1 R122.2 U1.AF10(STRAP_RESERVED10)
PLX_STRAP_RESERVED11: R124.2 U1.AD7(STRAP_RESERVED11)
PLX_STRAP_RESERVED12: R125.2 U1.AN4(STRAP_RESERVED12)
PLX_STRAP_RESERVED13: R126.2 U1.V7(STRAP_RESERVED13)
PLX_STRAP_RESERVED14: R127.2 U1.AE16(STRAP_RESERVED14)
PLX_STRAP_RESERVED15: R128.2 U1.AC7(STRAP_RESERVED15)
PLX_STRAP_RESERVED17: R129.2 U1.H16(STRAP_RESERVED17)
PLX_STRAP_SERDES_MODE_N: R132.2 U1.AG18(STRAP_SERDES_MODE_EN#)
PLX_STRAP_STN0_PORTCFG0: R159.1 R160.1 U1.AD8(STRAP_STN0_PORTCFG0)
PLX_STRAP_STN0_PORTCFG1: R161.1 R163.1 U1.AF11(STRAP_STN0_PORTCFG1)
PLX_STRAP_STN1_PORTCFG0: R169.1 R171.1 U1.H12(STRAP_STN1_PORTCFG0)
PLX_STRAP_STN1_PORTCFG1: R173.1 R174.1 U1.J10(STRAP_STN1_PORTCFG1)
PLX_STRAP_STN2_PORTCFG0: R175.1 R176.1 U1.AE21(STRAP_STN2_PORTCFG0)
PLX_STRAP_STN2_PORTCFG1: R177.1 R178.1 U1.AF23(STRAP_STN2_PORTCFG1)
PLX_STRAP_STN3_PORTCFG0: R179.1 R180.1 U1.K23(STRAP_STN3_PORTCFG0)
PLX_STRAP_STN3_PORTCFG1: R181.1 R182.1 U1.G25(STRAP_STN3_PORTCFG1)
PLX_STRAP_STN4_PORTCFG0: R185.1 R186.1 U1.AD26(STRAP_STN4_PORTCFG0)
PLX_STRAP_STN4_PORTCFG1: R187.1 R188.1 U1.N28(STRAP_STN4_PORTCFG1)
PLX_STRAP_STN5_PORTCFG0: R191.1 R192.1 U1.J28(STRAP_STN5_PORTCFG0)
PLX_STRAP_STN5_PORTCFG1: R193.1 R194.1 U1.K26(STRAP_STN5_PORTCFG1)
PLX_STRAP_TESTMODE: R139.1 R141.1 U1.H13(STRAP_TESTMODE)
PLX_STRAP_VS0_UPSTRM_PORTSEL0: R162.1 R164.1 U1.AE13(STRAP_VS0_UPSTRM_PORTSEL0)
PLX_STRAP_VS0_UPSTRM_PORTSEL1: R165.1 R166.1 U1.H10(STRAP_VS0_UPSTRM_PORTSEL1)
PLX_STRAP_VS0_UPSTRM_PORTSEL2: R167.1 R168.1 U1.K18(STRAP_VS0_UPSTRM_PORTSEL2)
PLX_STRAP_VS_MODE0: R92.2 R95.2 U1.AB8(STRAP_VS_MODE0)
PLX_STRAP_VS_MODE1: R100.2 R102.2 U1.AF16(STRAP_VS_MODE1)
TP_PLX2_REFCLK_SSC_N8: U3.AH11(PEX_REFCLK_SSCN8)
TP_PLX2_REFCLK_SSC_N9: U3.AH17(PEX_REFCLK_SSCN9)
TP_PLX2_REFCLK_SSC_N10: U3.AH21(PEX_REFCLK_SSCN10)
TP_PLX2_REFCLK_SSC_N11: U3.AH24(PEX_REFCLK_SSCN11)
TP_PLX2_REFCLK_SSC_P8: U3.AG11(PEX_REFCLK_SSCP8)
TP_PLX2_REFCLK_SSC_P9: U3.AG17(PEX_REFCLK_SSCP9)
TP_PLX2_REFCLK_SSC_P10: U3.AG21(PEX_REFCLK_SSCP10)
TP_PLX2_REFCLK_SSC_P11: U3.AG24(PEX_REFCLK_SSCP11)

Not connected (* = marked no-connect by the designer): U3 A2(NC0) A30(NC1) A33(NC2) AA6(NC29) AB1(NC30) AB2(NC31) AE7(PEX_REFCLK_SSCN1) AE8(PEX_REFCLK_SSCP1) AG9(PEX_REFCLK_SSCP3) AH7(PEX_REFCLK_SSCN2) AH8(PEX_REFCLK_SSCP2) AH9(PEX_REFCLK_SSCN3) B32(NC3) D2(NC4) F17(NC5) G7(PEX_REFCLK_SSCN4) G11(PEX_REFCLK_SSCN15) G14(PEX_REFCLK_SSCN14) G18(PEX_REFCLK_SSCN13) G19(NC6) G20(NC7) G22(PEX_REFCLK_SSCN12) H7(PEX_REFCLK_SSCP4) H11(PEX_REFCLK_SSCP15) H14(PEX_REFCLK_SSCP14) H18(PEX_REFCLK_SSCP13) H22(PEX_REFCLK_SSCP12) J7(PEX_REFCLK_SSCN5) J8(PEX_REFCLK_SSCP5) J16(NC8) J25(NC9) K20(NC10) K24(NC11) K29(NC12) L7(PEX_REFCLK_SSCN6) L8(PEX_REFCLK_SSCP6) M8(NC13) N27(NC14) N30(NC15) N31(NC16) N33(NC17) N34(NC18) P6(NC19) P27(NC20) P29(NC21) R29(NC22) T7(PEX_REFCLK_SSCN7) T8(PEX_REFCLK_SSCP7) T27(NC23) U7(NC24) U27(NC25) W7(NC26) Y6(NC27) Y7(PEX_REFCLK_SSCN0) Y8(PEX_REFCLK_SSCP0) Y27(NC28)

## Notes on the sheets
sheet 14
- 1U * 8 PCS
